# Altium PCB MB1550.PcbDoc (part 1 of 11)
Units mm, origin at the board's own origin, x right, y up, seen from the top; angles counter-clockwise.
Board outline 154.81 x 170.69 mm, 6 copper layers (Top Layer, Signal Layer 1, Signal Layer 2, Signal Layer 3, Signal Layer 4, Bottom Layer), stack 1.49 mm thick; 810 components, 633 nets, 2973 pads, 2150 vias.
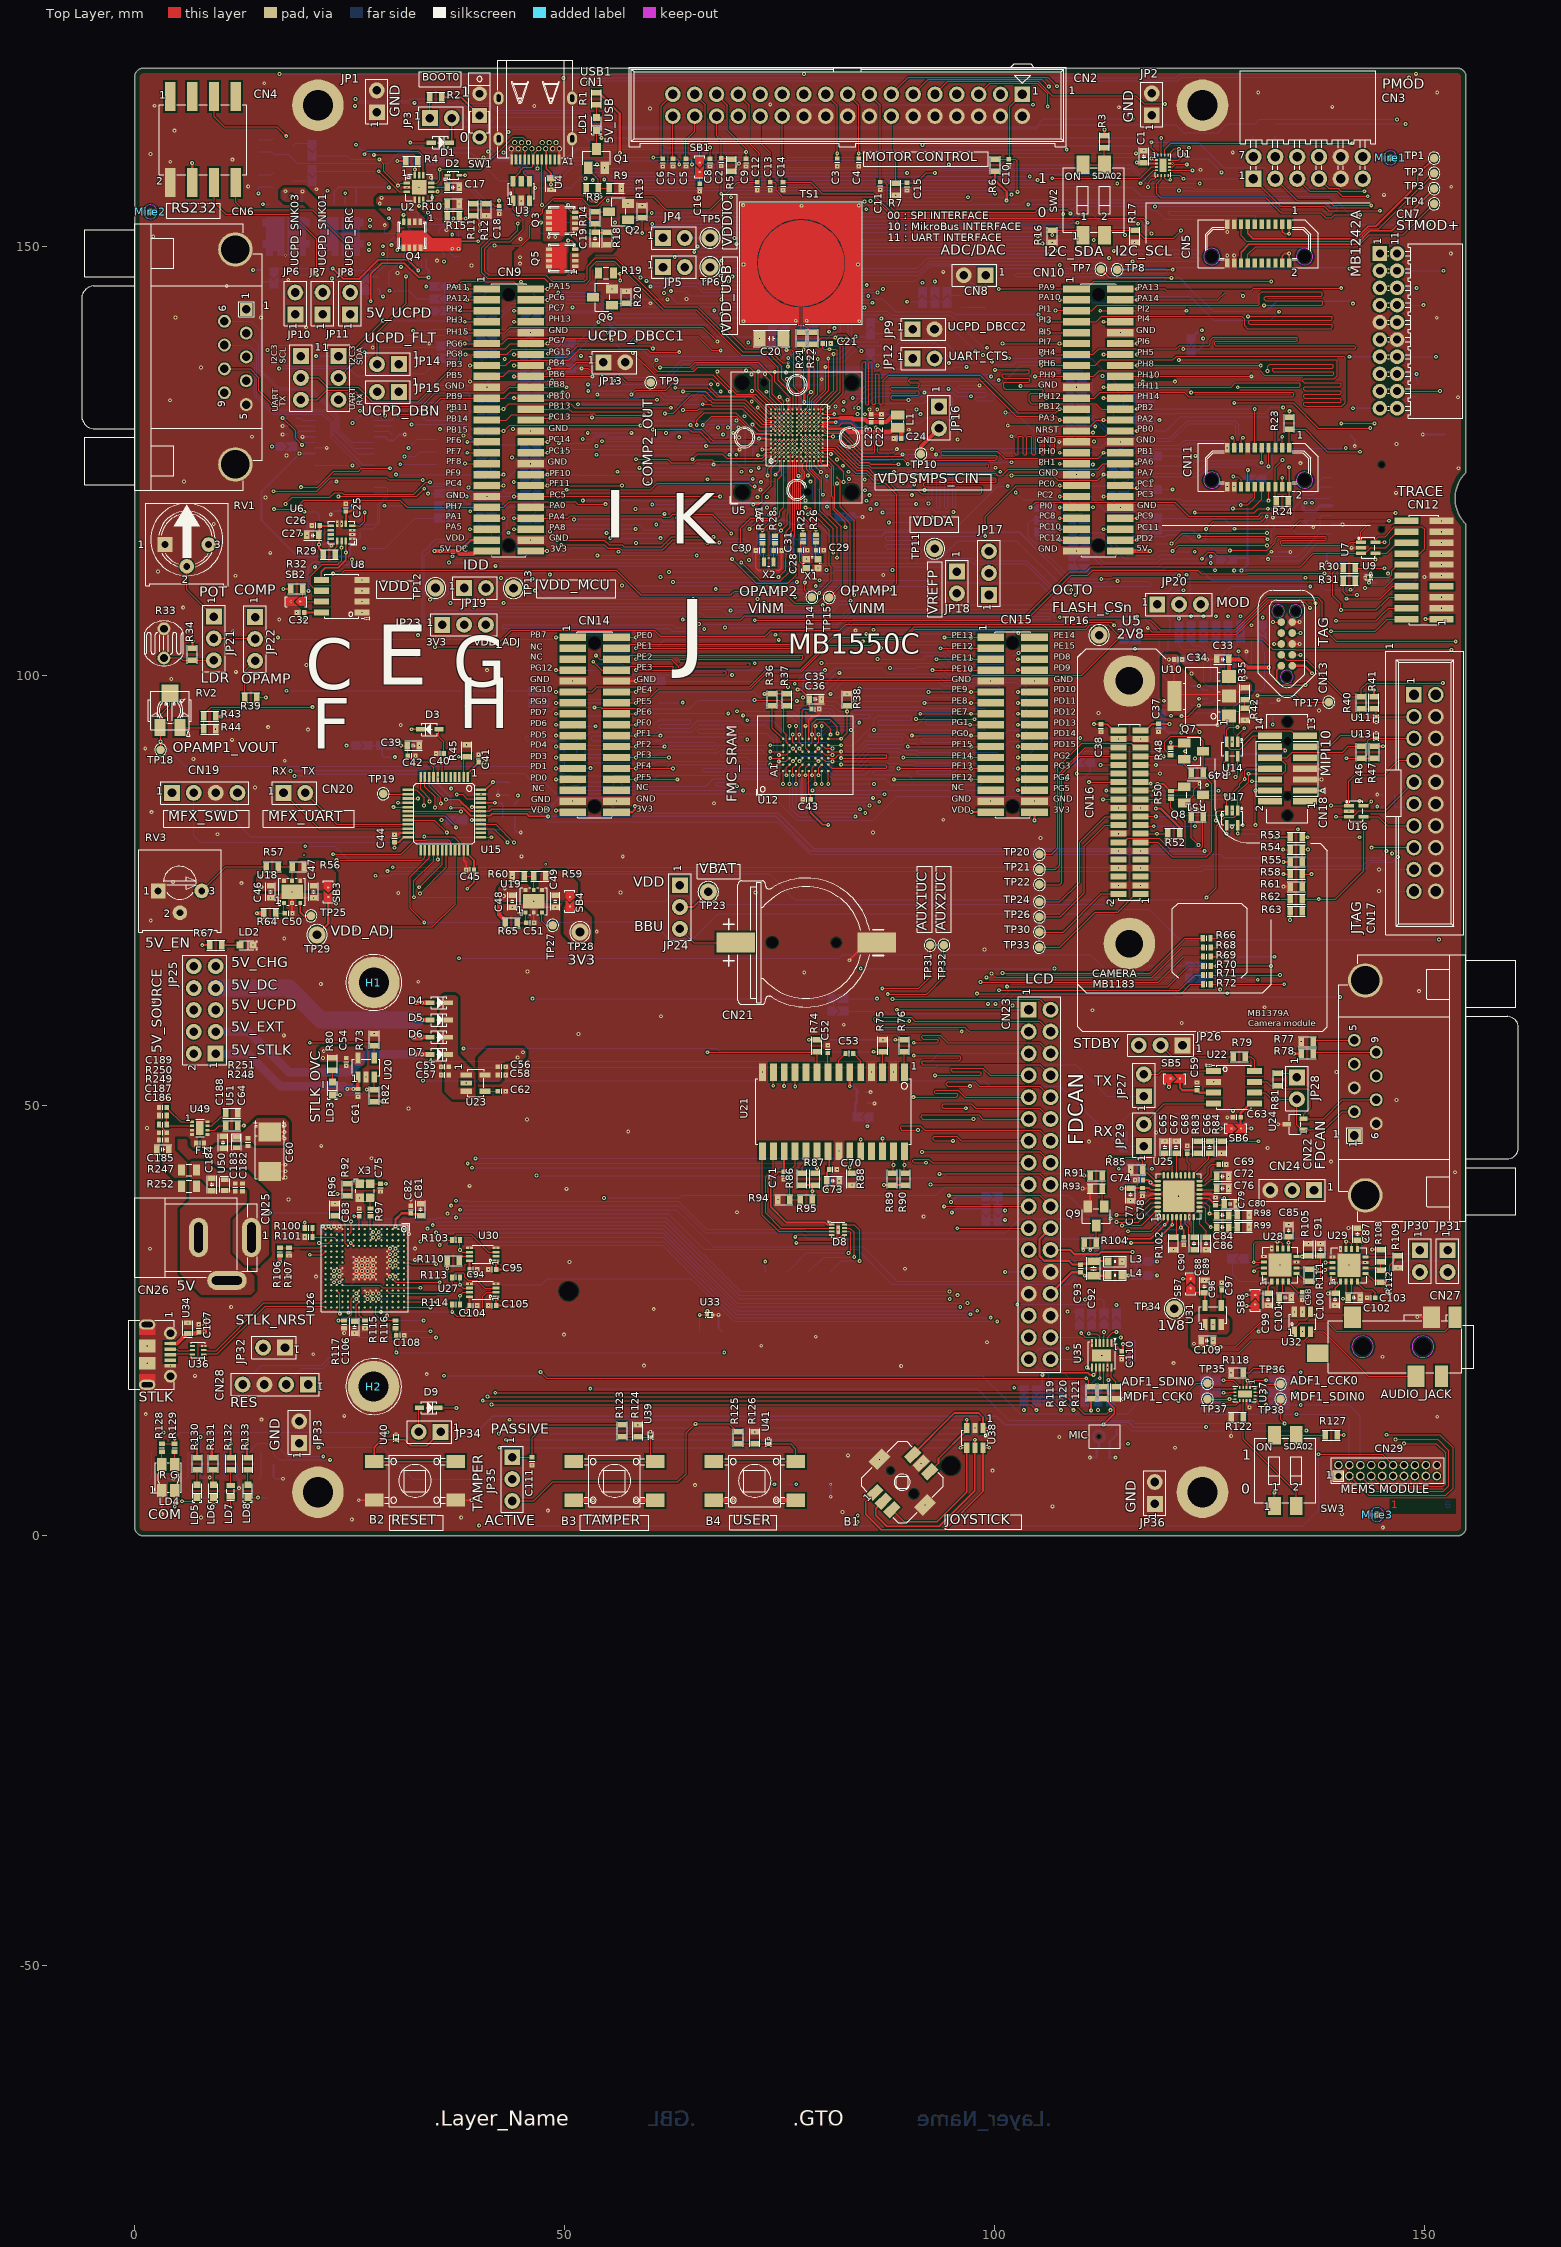
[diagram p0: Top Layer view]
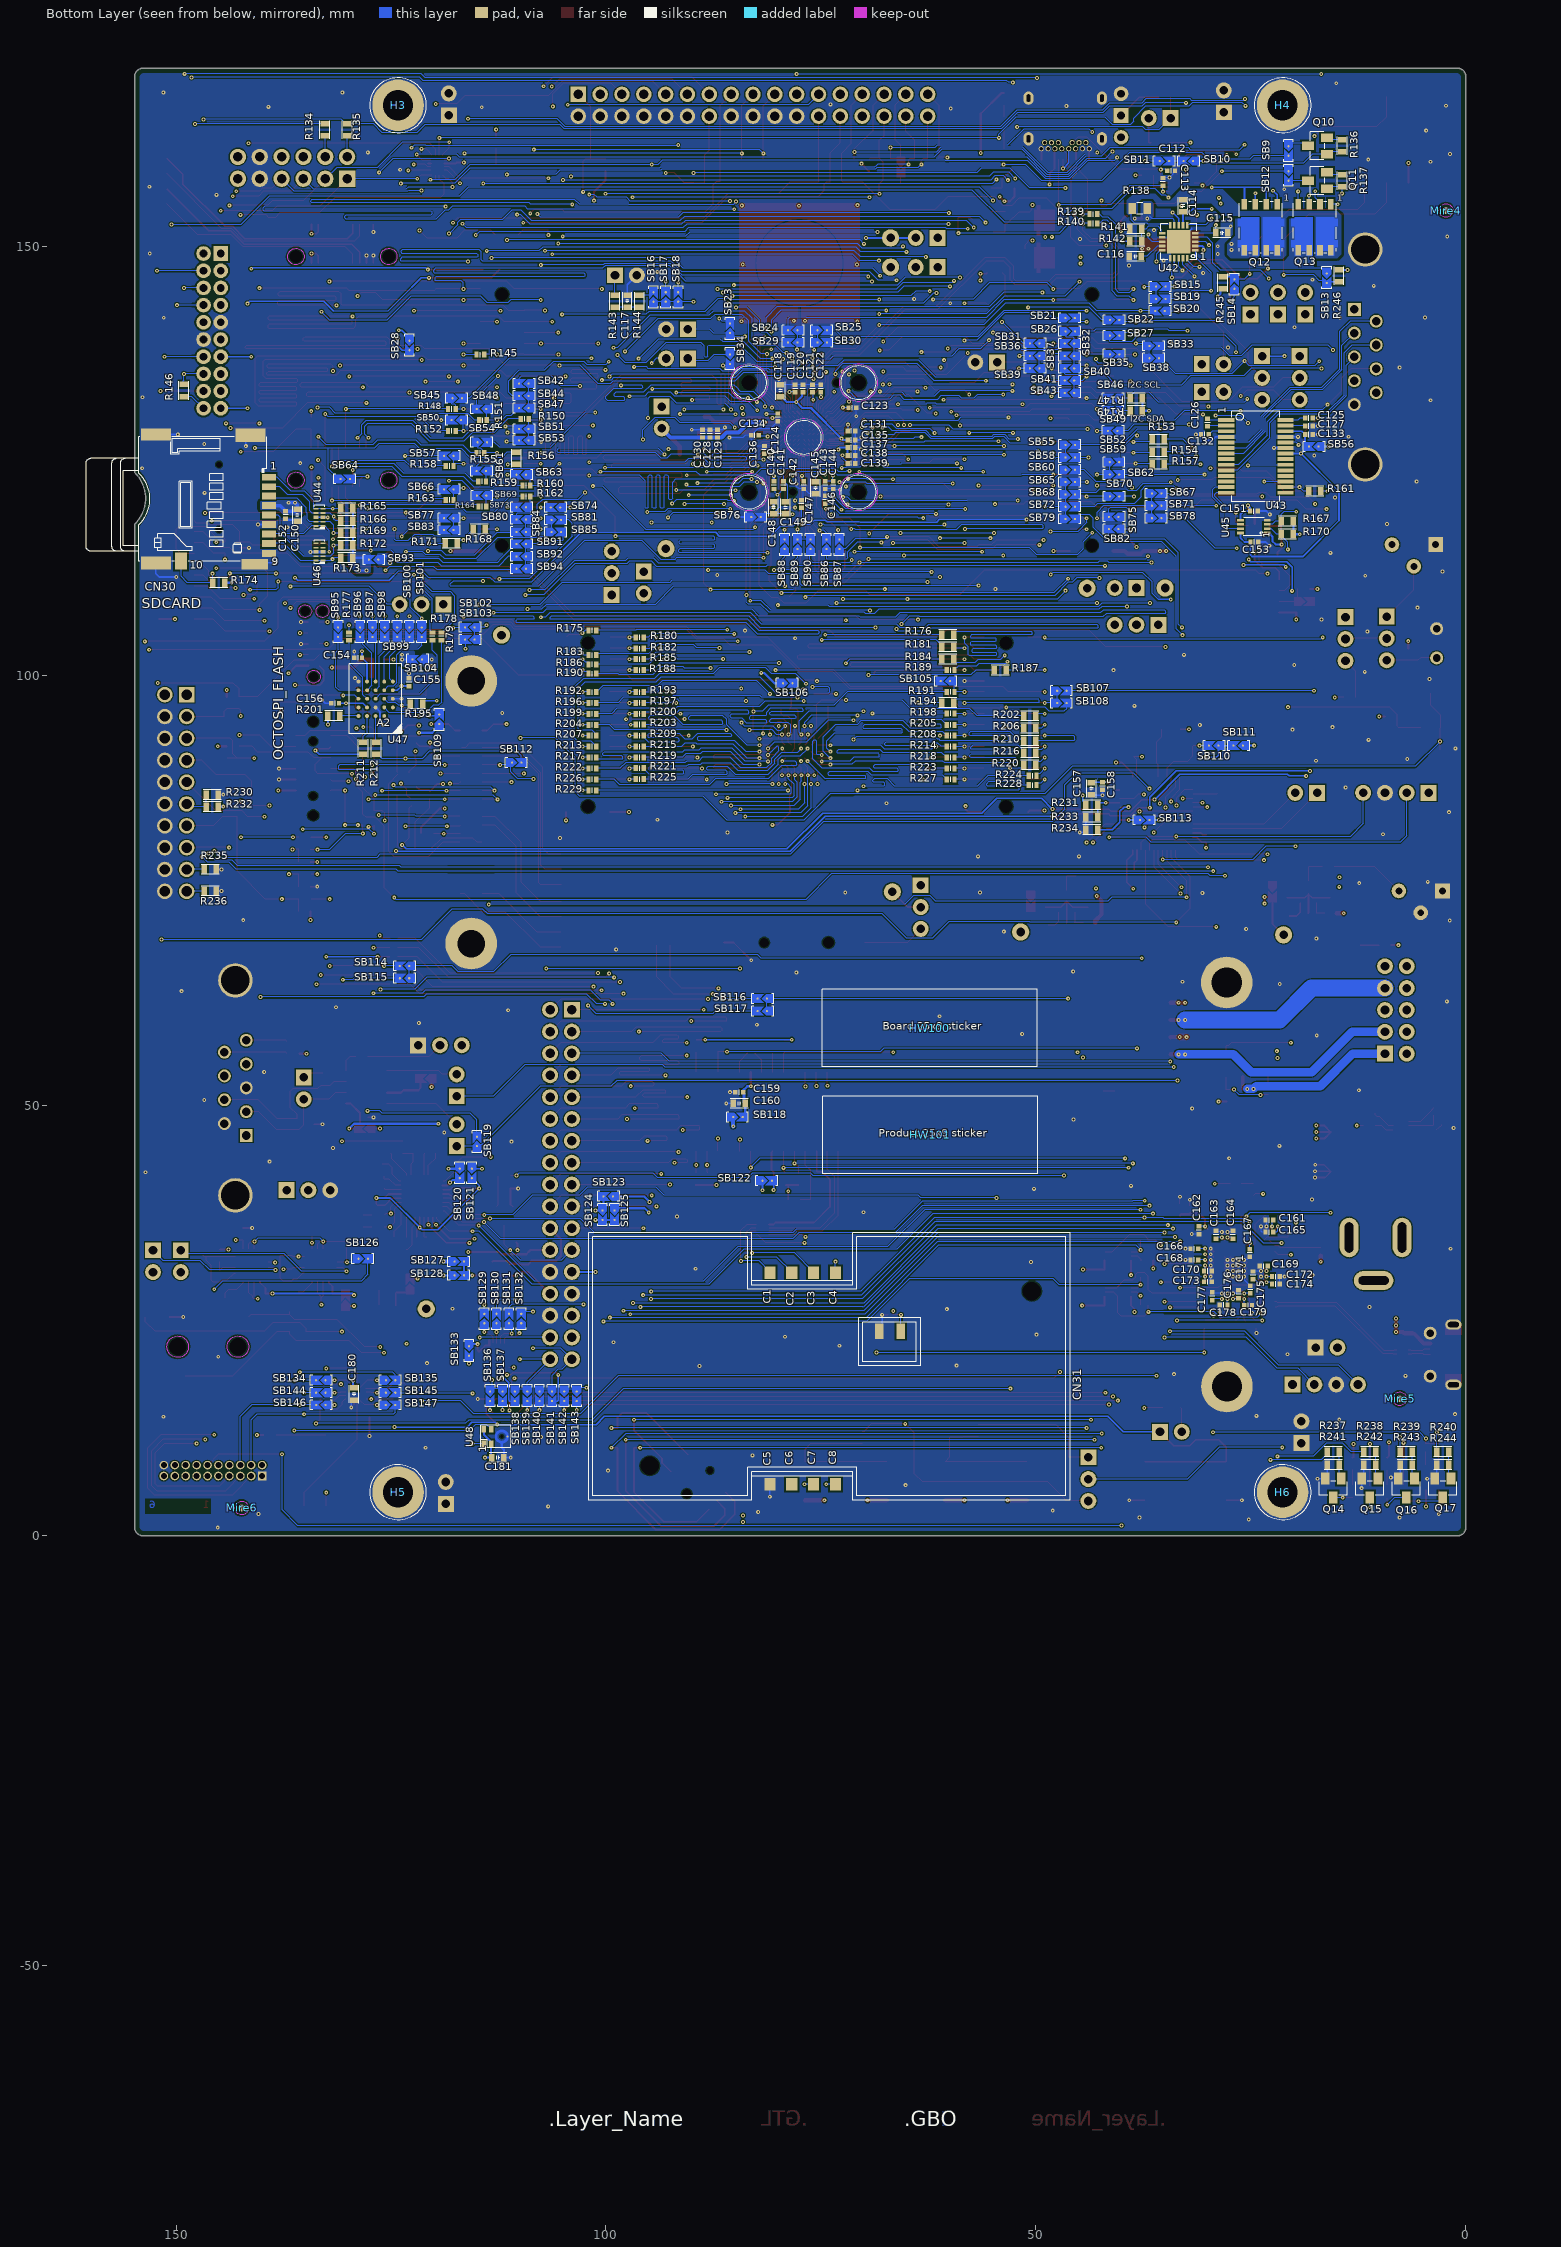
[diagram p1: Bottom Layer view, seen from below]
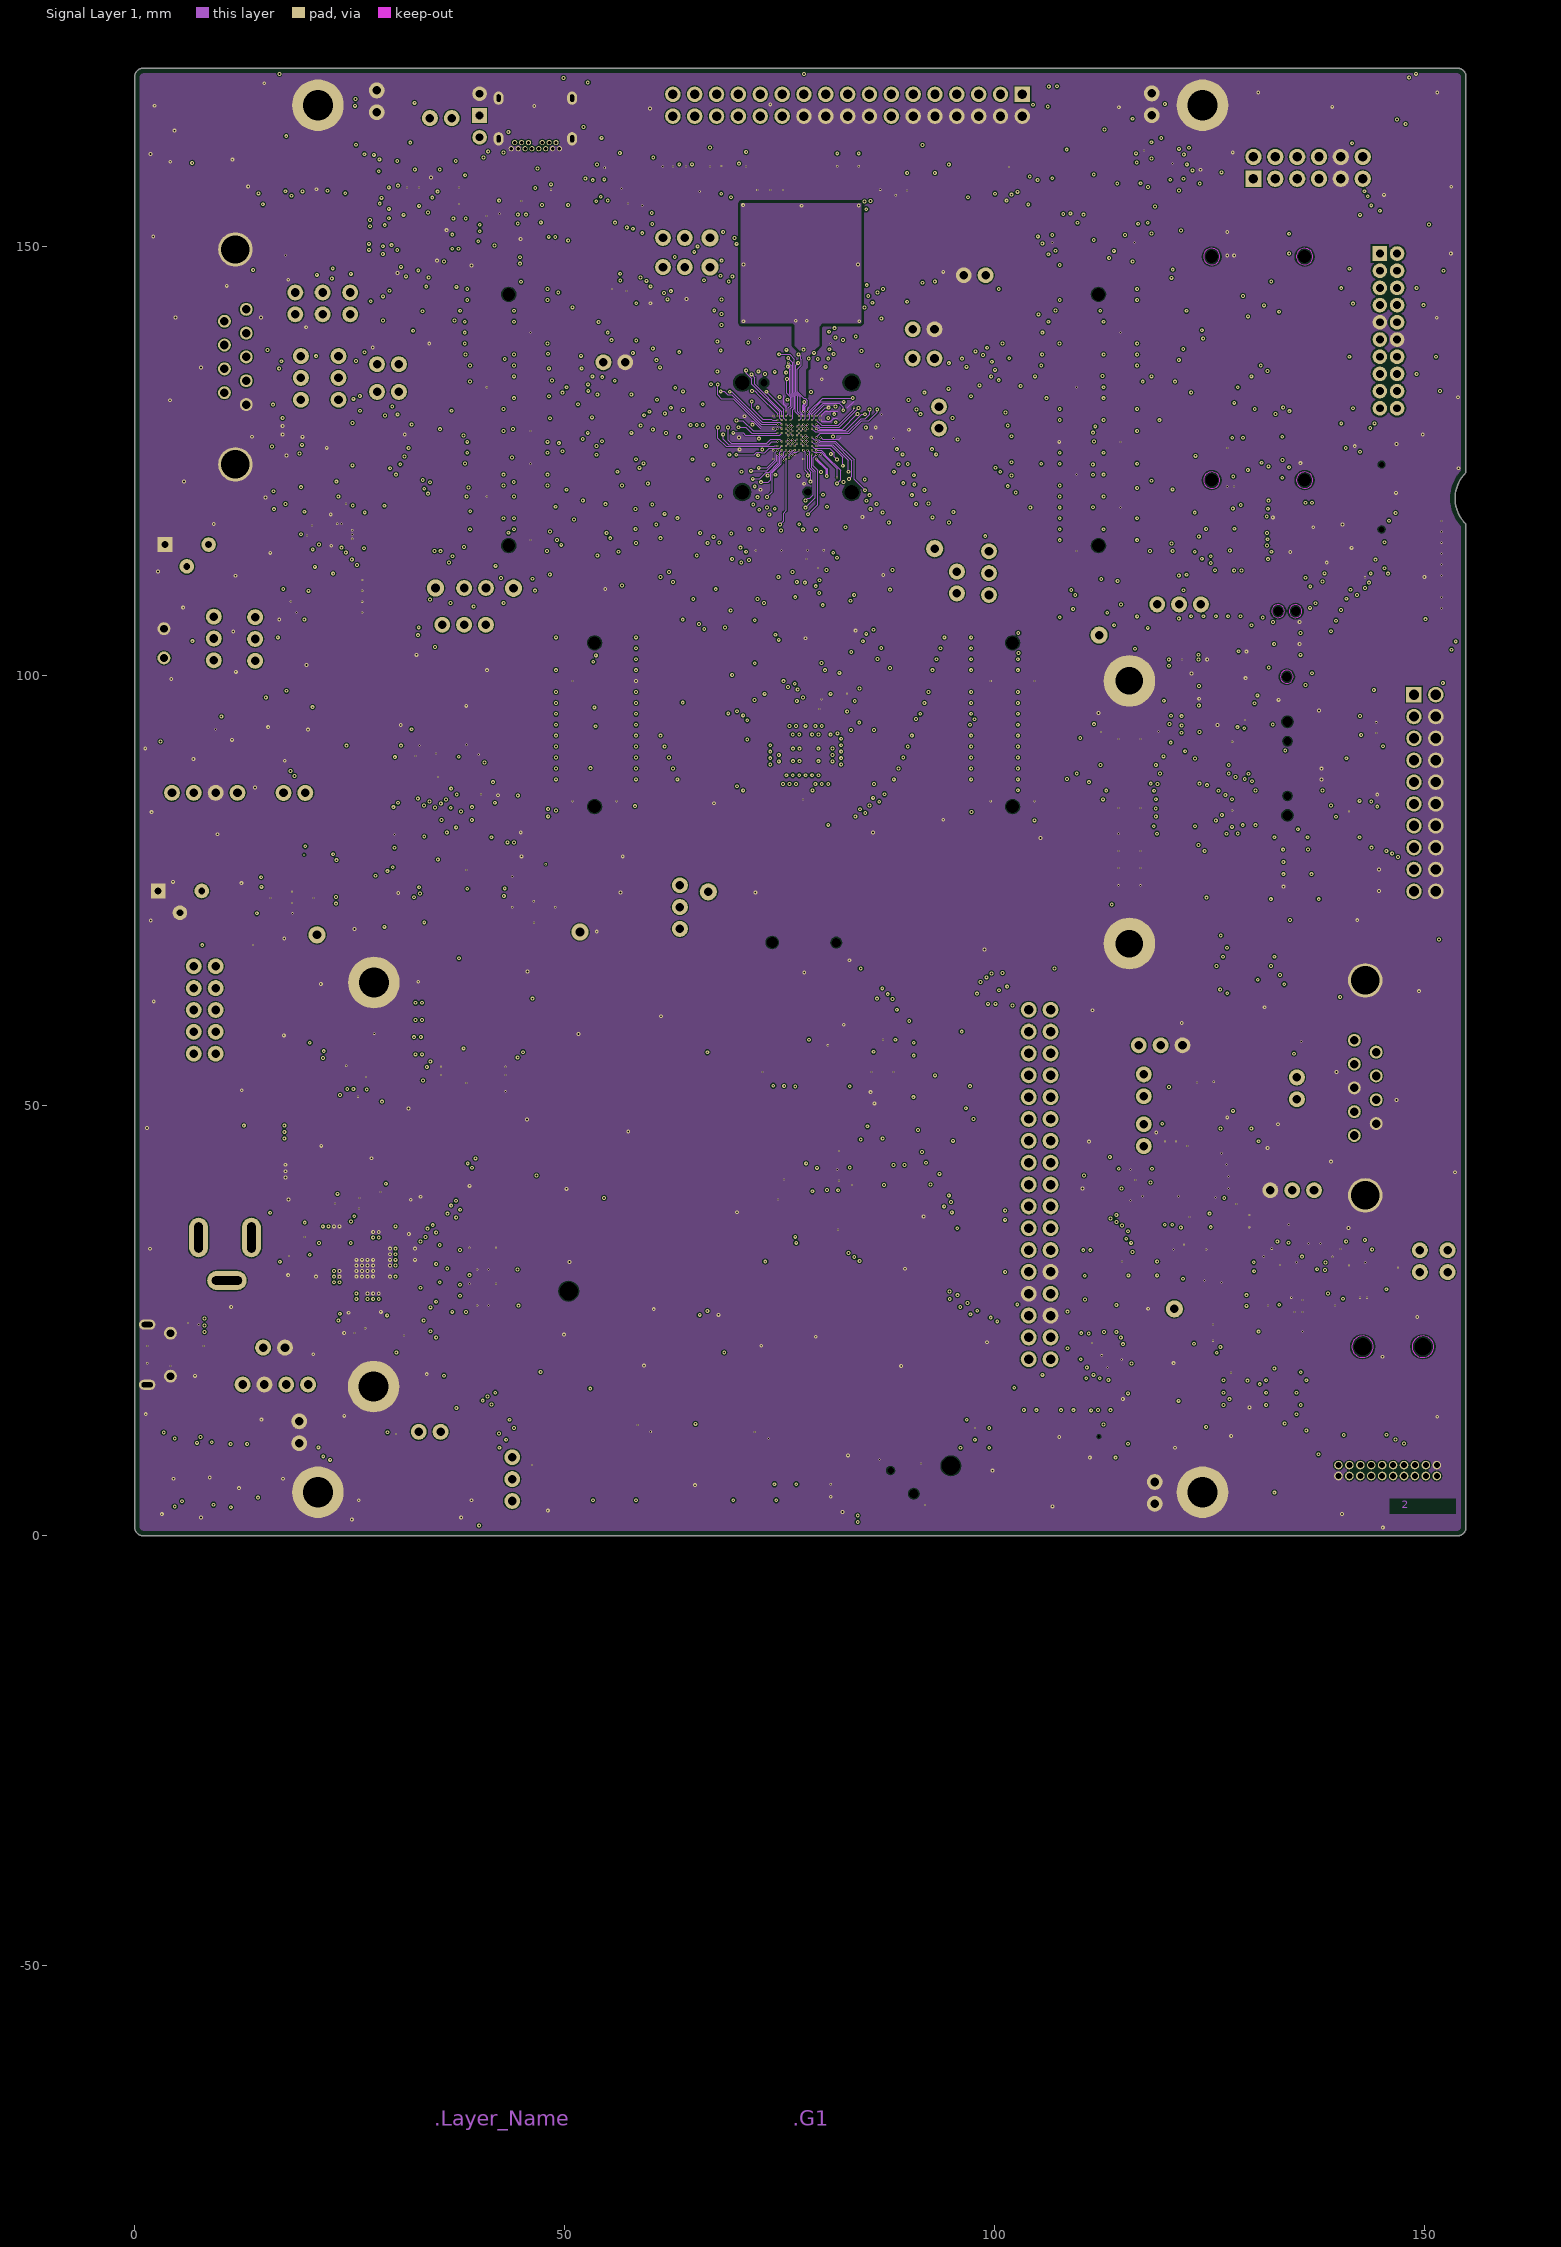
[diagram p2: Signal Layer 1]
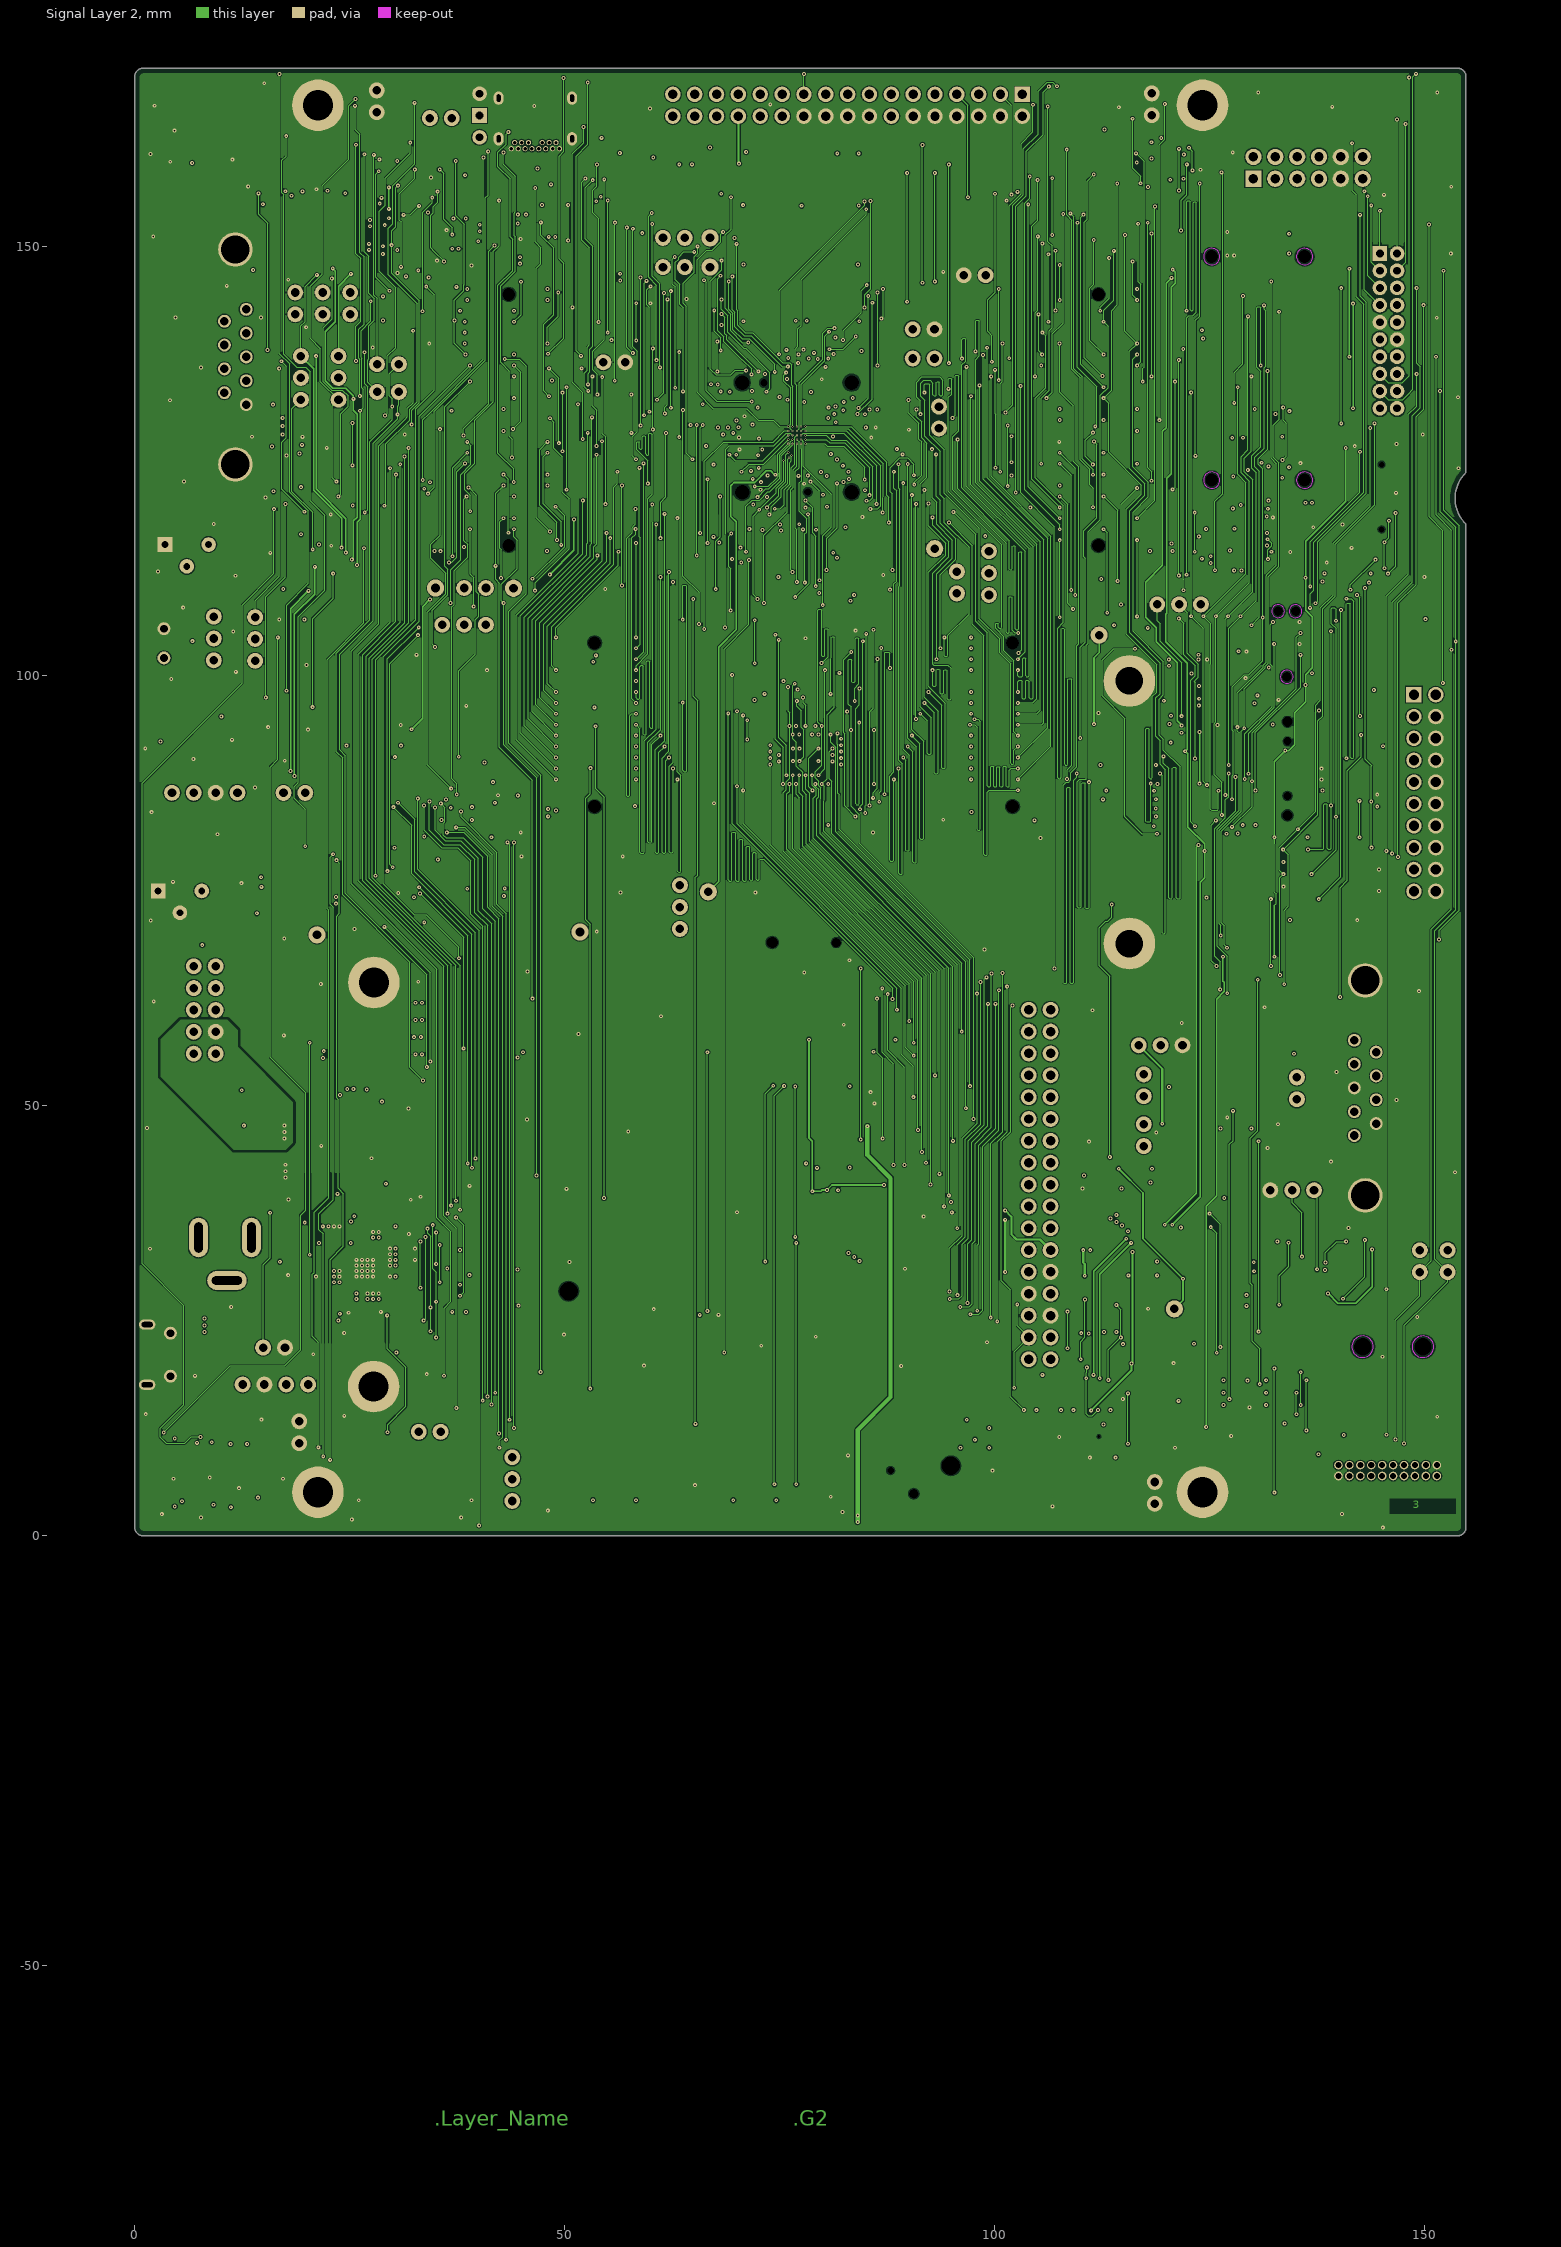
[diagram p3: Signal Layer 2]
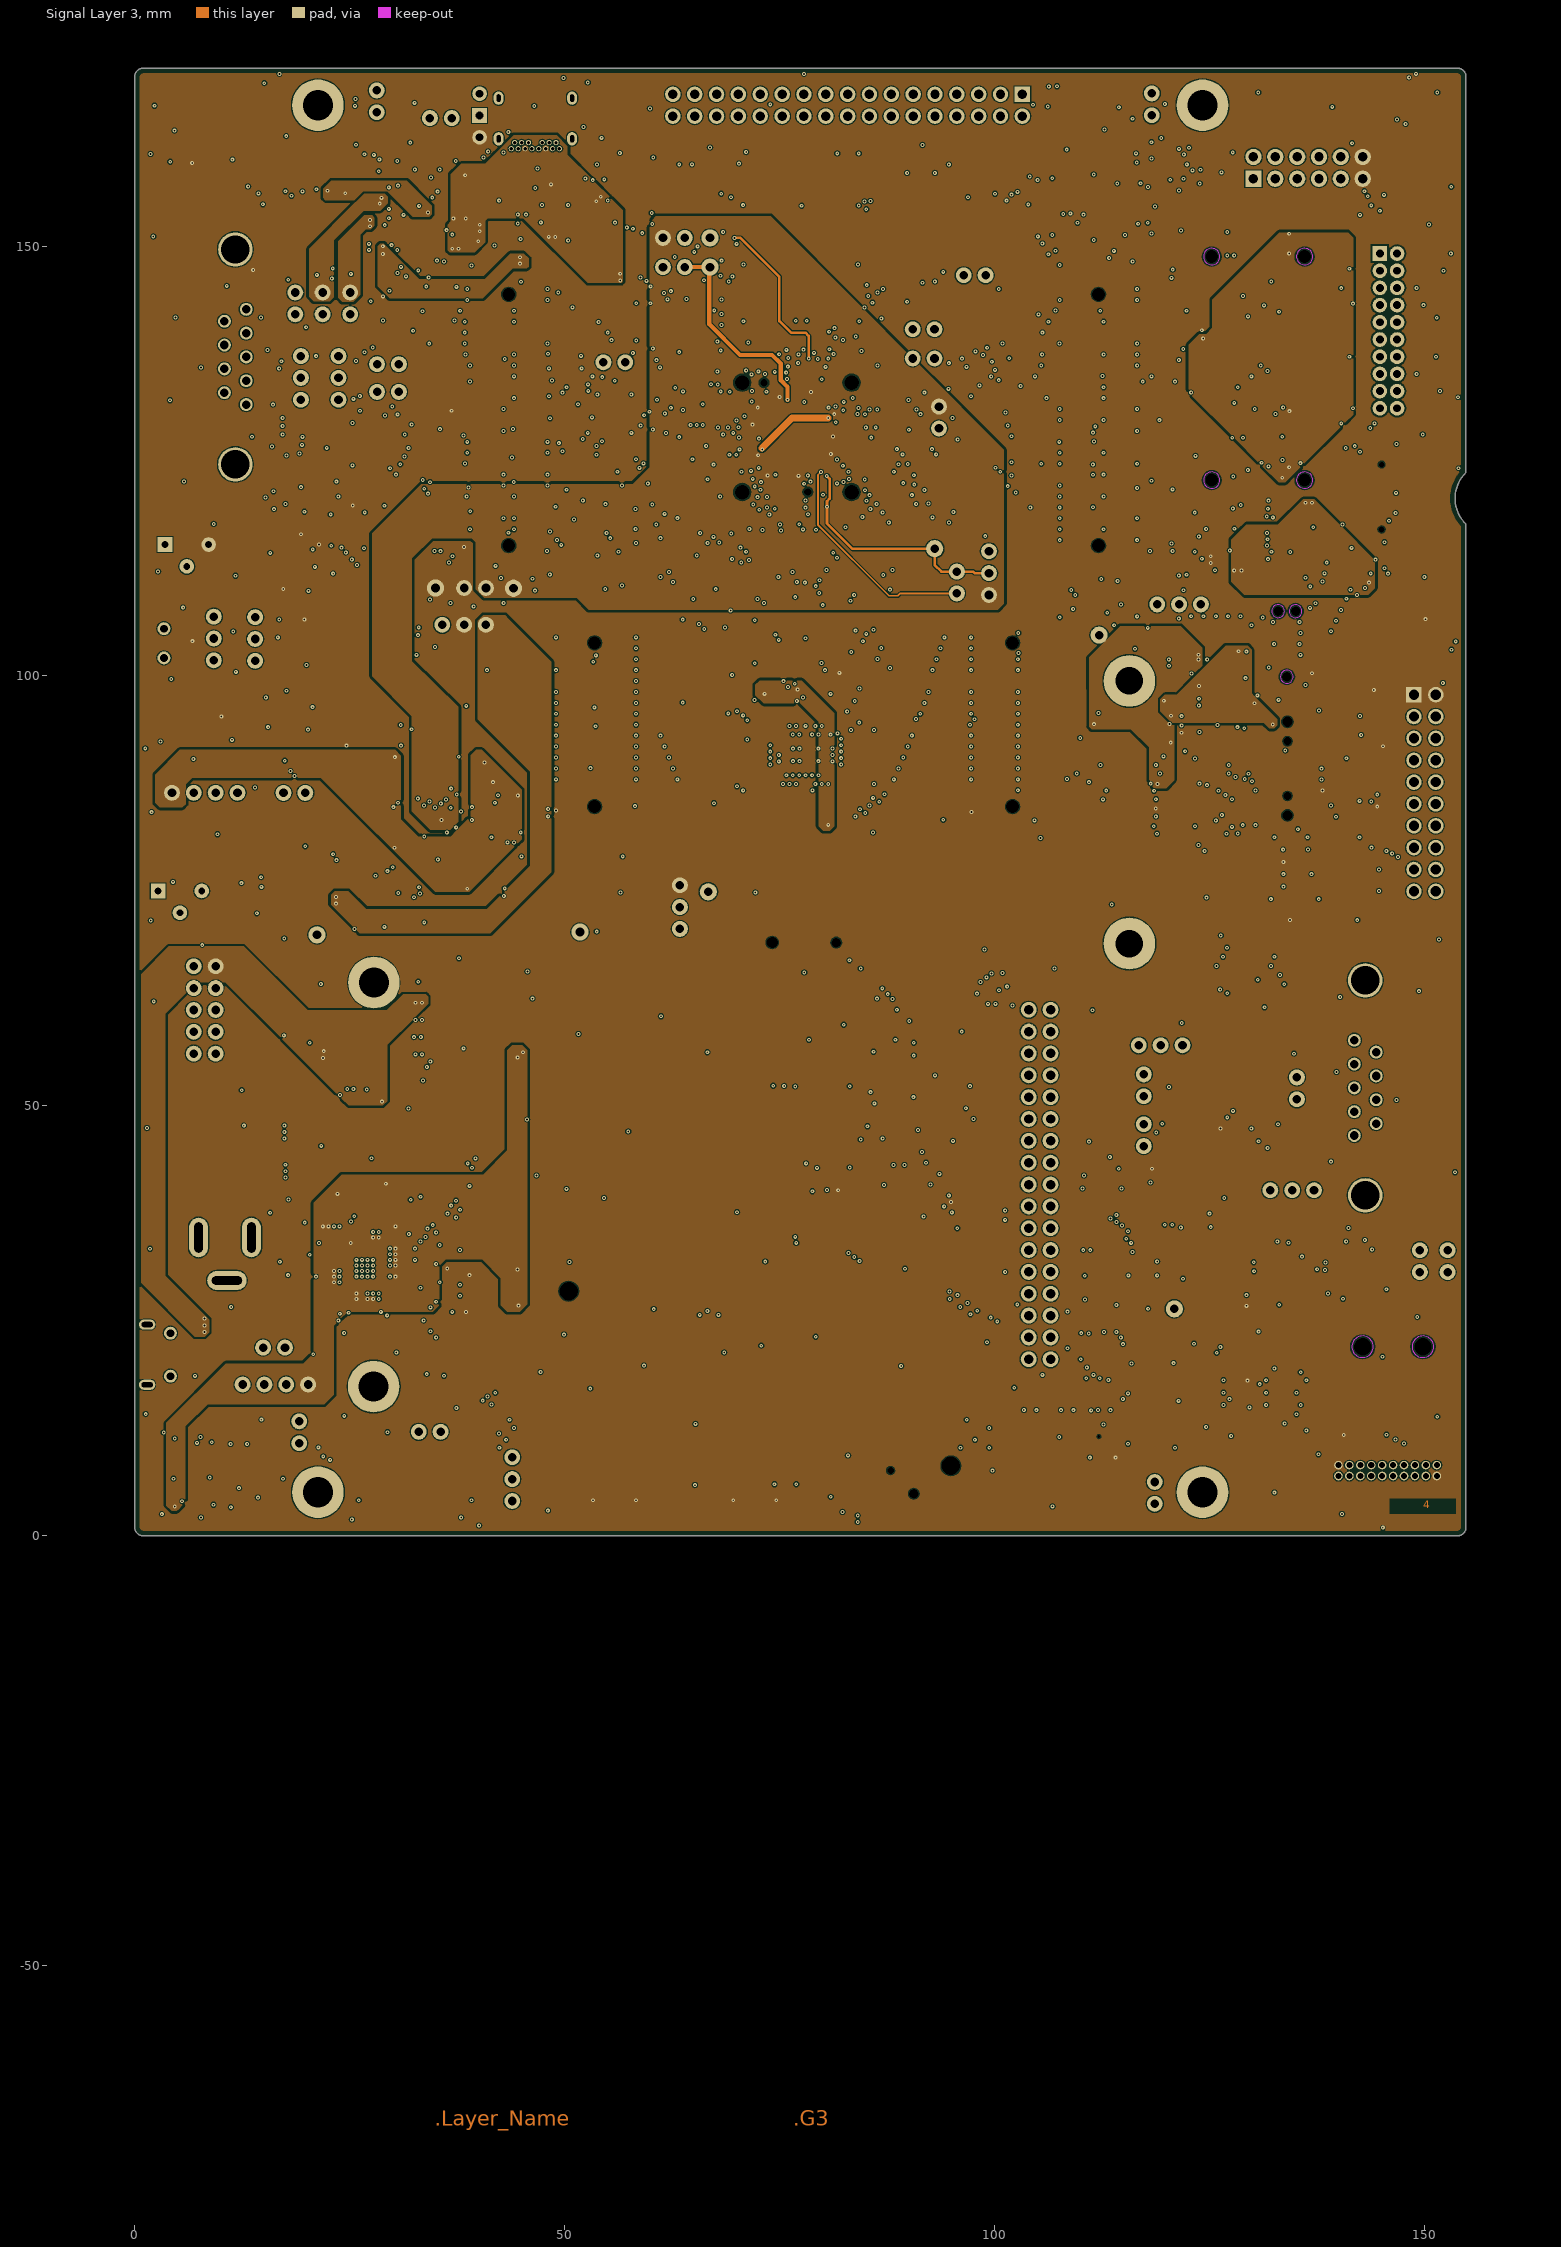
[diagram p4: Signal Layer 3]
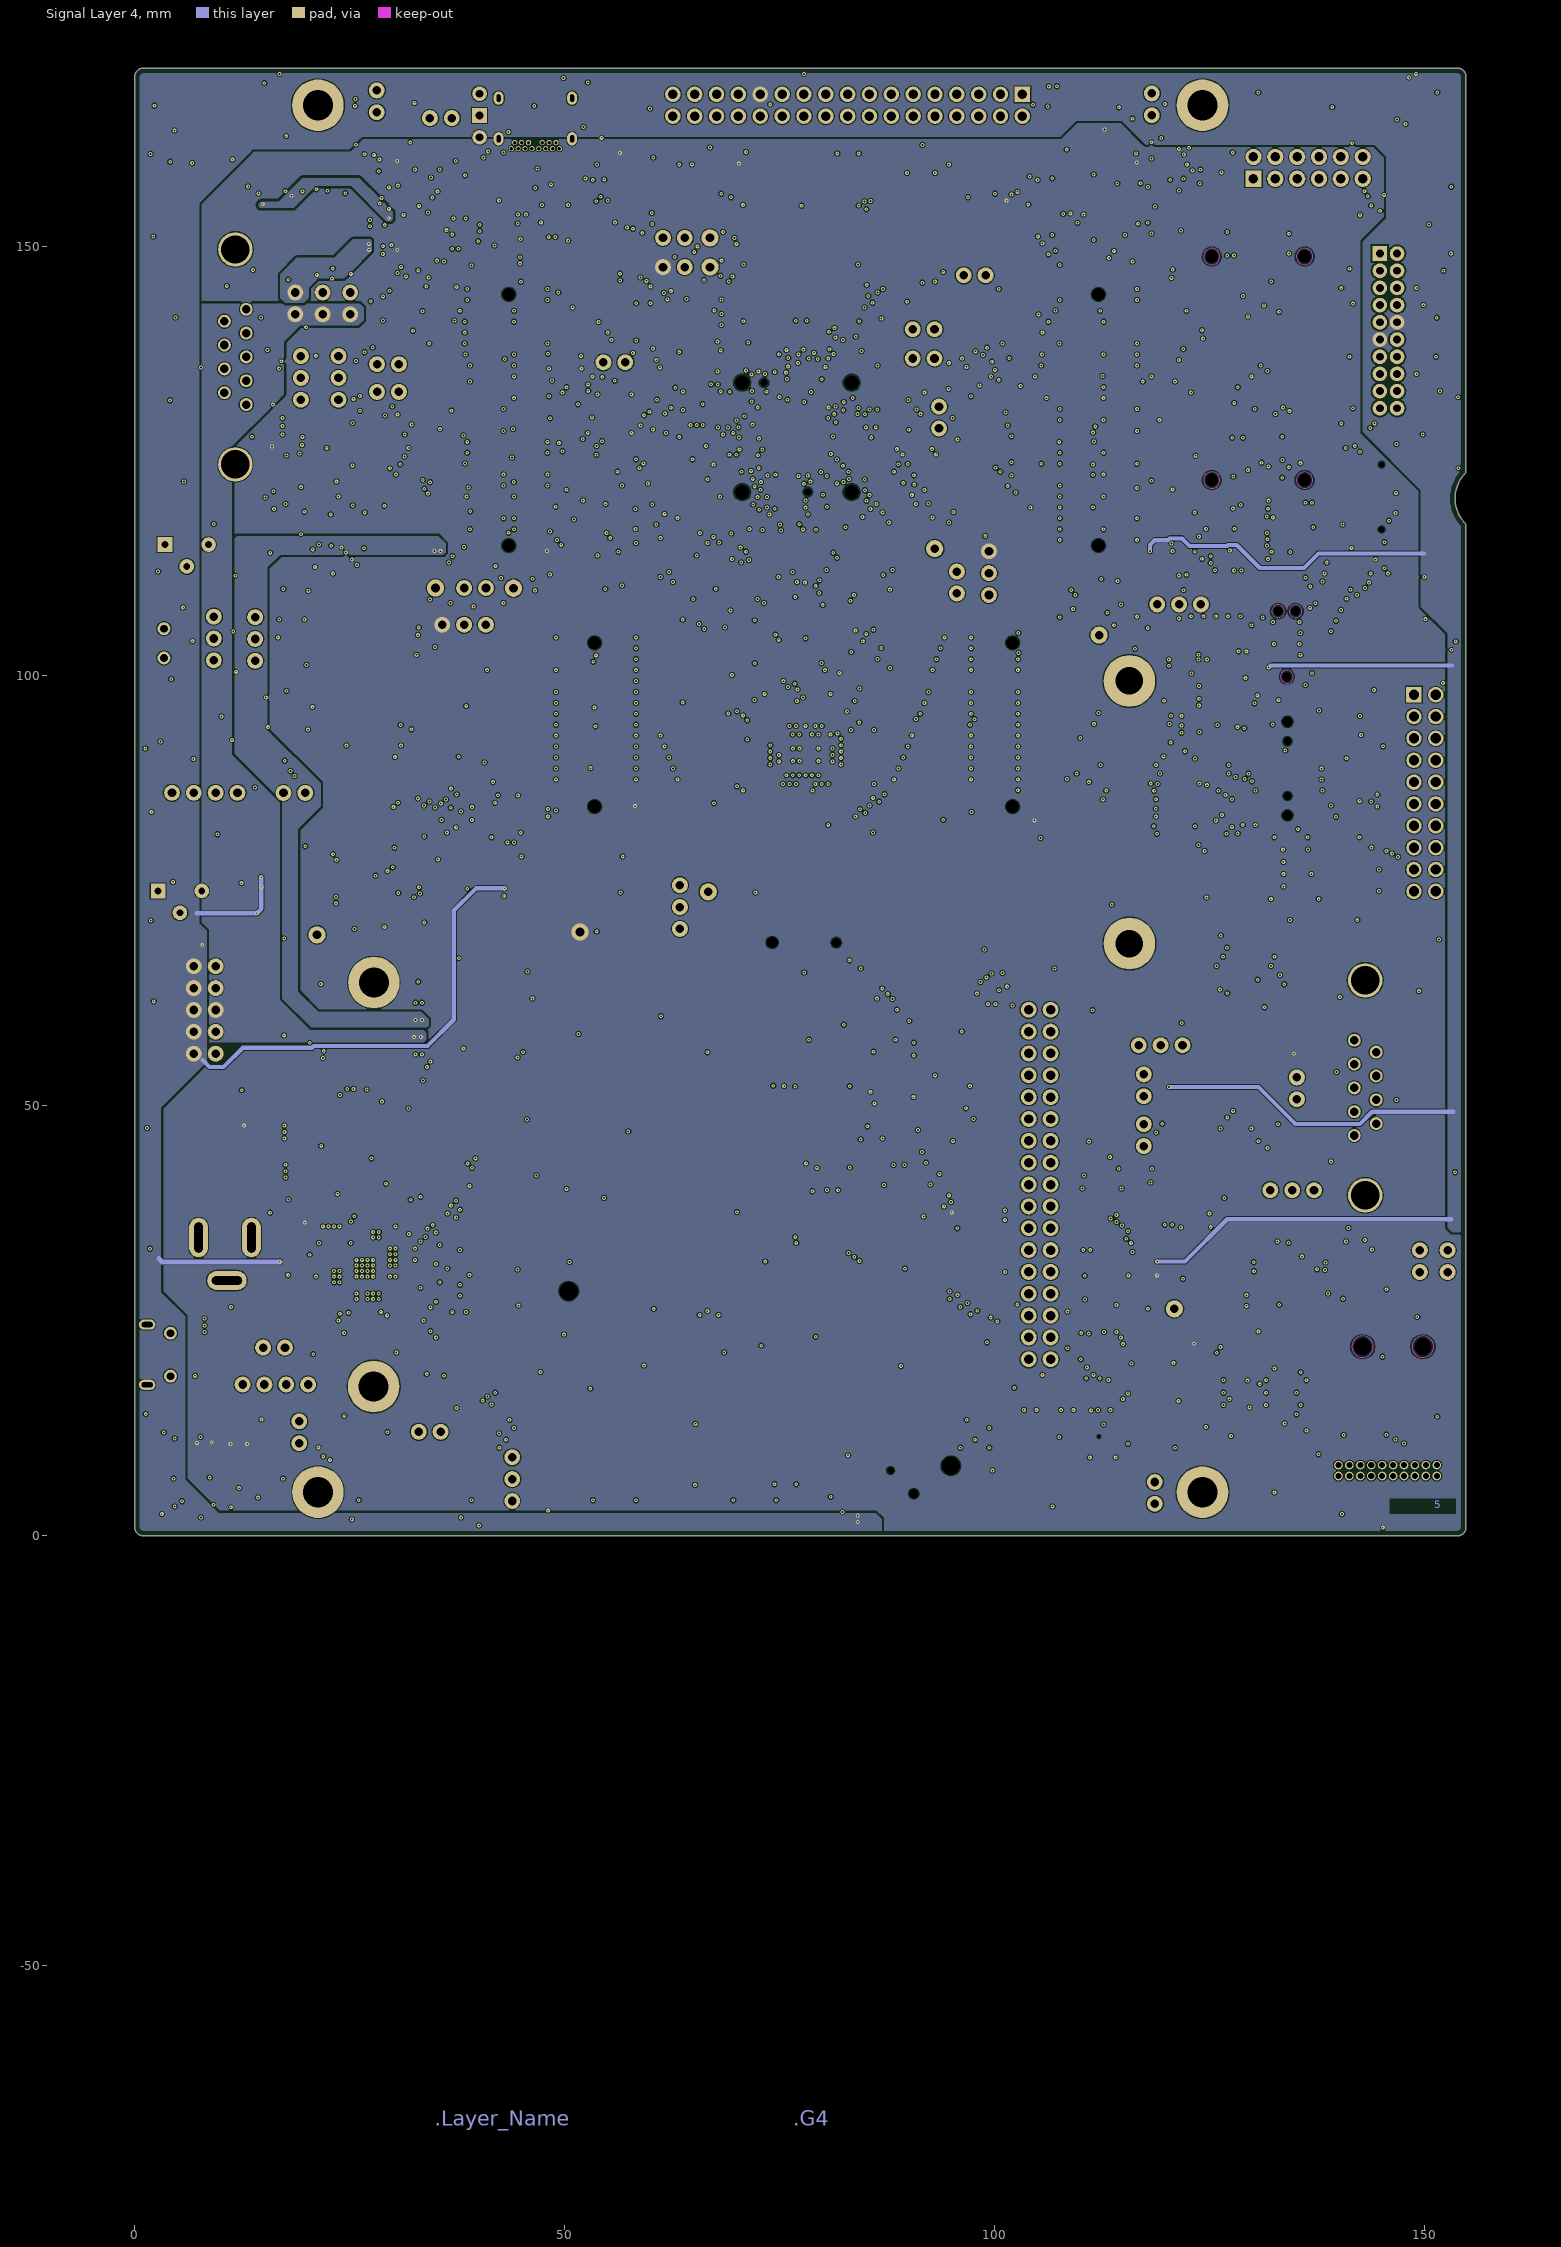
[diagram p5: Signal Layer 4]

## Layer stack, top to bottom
Top Solder: solder mask 0.015, Solder Resist, Dk 3.5
Top Layer: signal copper 0.035
Dielectric 1: prepreg 0.07, TU-768P, Dk 4.2
Signal Layer 1: signal copper 0.035
Dielectric 2: core 0.07, TU-768P, Dk 4.2
Signal Layer 2: signal copper 0.035
Dielectric 3: prepreg 1, TU-768, Dk 4.2
Signal Layer 3: signal copper 0.035
Dielectric 4: core 0.07, TU-768P, Dk 4.2
Signal Layer 4: signal copper 0.035
Dielectric 5: prepreg 0.07, TU-768P, Dk 4.2
Bottom Layer: signal copper 0.035
Bottom Solder: solder mask 0.015, Solder Resist, Dk 3.5

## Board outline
0,1 ccw(c1,1) 1,0 153.813,0 ccw(c153.813,1) 154.813,1 154.813,117.648 154.811,117.648 cw(c157.726,120.648) 154.813,123.65 154.813,169.688 ccw(c153.813,169.688) 153.813,170.688 1,170.688 ccw(c1,169.688) 0,169.688

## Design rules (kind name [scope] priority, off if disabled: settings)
BoardOutlineClearance BoardOutlineClearance_2 [OnLayer('Bottom Overlay')] p1: gap=0 ignorepadtopadclearanceinfootprint=FALSE
BoardOutlineClearance BoardOutlineClearance_1 [OnLayer('Top Overlay')] p2: gap=0 ignorepadtopadclearanceinfootprint=FALSE
BoardOutlineClearance [All] p3: gap=0.6 ignorepadtopadclearanceinfootprint=FALSE
Clearance Clearance_BGA_MCU [WithinRoom('RoomDefinition')and TouchesRoom('RoomDefinition')] p1: gap=0.085 ignorepadtopadclearanceinfootprint=TRUE except(0: Arc-Hole Track-Hole SMDPad-Hole THPad-Hole Via-Hole Fill-Hole Poly-Hole Region-Hole Text-Hole; 0.12: Via-Poly; 0.14: Track-Poly; 0.15: SMDPad-SMDPad; 0.2: Arc-Fill Arc-Poly Track-Fill SMDPad-THPad SMDPad-Fill SMDPad-Poly THPad-THPad THPad-Fill THPad-Poly Via-Fill Fill-Poly; 0.3: Fill-Fill Poly-Poly)
Clearance Clearance_BGA_SRAM [WithinRoom('RoomDefinition_1')and TouchesRoom('RoomDefinition_1')] p2: gap=0.09 ignorepadtopadclearanceinfootprint=TRUE except(0: Arc-Hole Track-Hole SMDPad-Hole THPad-Hole Via-Hole Fill-Hole Poly-Hole Region-Hole Text-Hole; 0.12: Via-Poly; 0.15: SMDPad-SMDPad; 0.2: Arc-Fill Arc-Poly Track-Fill Track-Poly SMDPad-THPad SMDPad-Fill SMDPad-Poly THPad-THPad THPad-Fill THPad-Poly Via-Fill Fill-Poly; 0.3: Fill-Fill Poly-Poly)
Clearance Clearance_BGA_STLINK [WithinRoom('RoomDefinition_2')and TouchesRoom('RoomDefinition_2')] p3: gap=0.09 ignorepadtopadclearanceinfootprint=TRUE except(0: Arc-Hole Track-Hole SMDPad-Hole THPad-Hole Via-Hole Fill-Hole Poly-Hole Region-Hole Text-Hole; 0.12: Via-Poly; 0.15: SMDPad-SMDPad; 0.2: Arc-Fill Arc-Poly Track-Fill Track-Poly SMDPad-THPad SMDPad-Fill SMDPad-Poly THPad-THPad THPad-Fill THPad-Poly Via-Fill Fill-Poly; 0.3: Fill-Fill Poly-Poly)
Clearance Clearance_CONN [WithinRoom('RoomDefinition_3','RoomDefinition_4')and TouchesRoom('RoomDefinition_3','RoomDefinition_4')] p4: gap=0.1 ignorepadtopadclearanceinfootprint=TRUE except(0: Arc-Hole Track-Hole SMDPad-Hole THPad-Hole Via-Hole Fill-Hole Poly-Hole Region-Hole Text-Hole; 0.12: Via-Poly; 0.15: SMDPad-SMDPad; 0.2: Arc-Fill Arc-Poly Track-Fill Track-Poly SMDPad-THPad SMDPad-Fill SMDPad-Poly THPad-THPad THPad-Fill THPad-Poly Via-Fill Fill-Poly; 0.3: Fill-Fill Poly-Poly)
Clearance Clearance_50Ohms [InNetClass('50 Ohms')] p5: gap=0.12 ignorepadtopadclearanceinfootprint=TRUE except(0: Arc-Hole Track-Hole SMDPad-Hole THPad-Hole Via-Hole Fill-Hole Poly-Hole Region-Hole Text-Hole; 0.15: SMDPad-SMDPad; 0.2: Arc-Fill Arc-Poly SMDPad-THPad SMDPad-Fill SMDPad-Poly THPad-THPad THPad-Fill Via-Via Via-Fill Fill-Poly; 0.23: Arc-Track Track-Track; 0.29: Track-Fill Track-Poly; 0.3: Fill-Fill Poly-Poly)
Clearance [All] p6: gap=0.12 ignorepadtopadclearanceinfootprint=TRUE except(0: Arc-Hole Track-Hole SMDPad-Hole THPad-Hole Via-Hole Fill-Hole Poly-Hole Region-Hole Text-Hole; 0.15: SMDPad-SMDPad; 0.2: Arc-Fill Arc-Poly Track-Fill SMDPad-THPad SMDPad-Fill SMDPad-Poly THPad-THPad THPad-Fill Via-Via Via-Fill Fill-Poly; 0.3: Fill-Fill Poly-Poly)
ComponentClearance [All] p1 off: gap=0.025 collisioncheckmode=3 verticalgap=0 showdistances=FALSE
DiffPairsRouting DiffPairsRouting_90_ohms [InDifferentialPairClass('90Ohms_Diff')] p1: maxlimit=0.26 minlimit=0.251 mostfreqgap=0.251 toplayer_mingap=0.26 toplayer_prefgap=0.26 toplayer_minwidth=0.12 toplayer_maxwidth=0.12 toplayer_prefwidth=0.12 midlayer1_maxgap=0.251 midlayer1_minwidth=0.13 midlayer1_maxwidth=0.13 midlayer1_prefwidth=0.13 midlayer2_maxgap=0.251 midlayer2_minwidth=0.13 midlayer2_maxwidth=0.13 midlayer2_prefwidth=0.13 midlayer3_maxgap=0.251 midlayer3_minwidth=0.13 midlayer3_maxwidth=0.13 midlayer3_prefwidth=0.13 midlayer4_maxgap=0.251 midlayer4_minwidth=0.13 midlayer4_maxwidth=0.13 midlayer4_prefwidth=0.13 bottomlayer_mingap=0.26 bottomlayer_prefgap=0.26 bottomlayer_minwidth=0.12 bottomlayer_maxwidth=0.12 bottomlayer_prefwidth=0.12 maxuncoupledlength=12.7
DiffPairsRouting DiffPairsRouting_100_ohms [InDifferentialPairClass('100Ohms_Diff')] p2: maxlimit=0.277 minlimit=0.251 mostfreqgap=0.277 toplayer_maxgap=0.251 toplayer_prefgap=0.251 toplayer_minwidth=0.13 toplayer_maxwidth=0.13 toplayer_prefwidth=0.13 midlayer1_mingap=0.277 midlayer1_minwidth=0.104 midlayer1_maxwidth=0.104 midlayer1_prefwidth=0.104 midlayer2_mingap=0.277 midlayer2_minwidth=0.104 midlayer2_maxwidth=0.104 midlayer2_prefwidth=0.104 midlayer3_mingap=0.277 midlayer3_minwidth=0.104 midlayer3_maxwidth=0.104 midlayer3_prefwidth=0.104 midlayer4_mingap=0.277 midlayer4_minwidth=0.104 midlayer4_maxwidth=0.104 midlayer4_prefwidth=0.104 bottomlayer_maxgap=0.251 bottomlayer_prefgap=0.251 bottomlayer_minwidth=0.13 bottomlayer_maxwidth=0.13 bottomlayer_prefwidth=0.13 maxuncoupledlength=12.7
FanoutControl Fanout_LCC [IsLCC] p1: bgadir=Out bgaviamode=Centered fanoutstyle=Auto fanoutdirection=Alternating viagrid=0.025 // Fanout_LCC (Default Rule)
FanoutControl Fanout_SOIC [IsSOIC] p2: bgadir=Out bgaviamode=Centered fanoutstyle=Auto fanoutdirection=Alternating viagrid=0.025 // Fanout_SOIC (Default Rule)
FanoutControl Fanout_Small [(CompPinCount < 5)] p3: bgadir=Out bgaviamode=Centered fanoutstyle=Auto fanoutdirection=OutThenIn viagrid=0.025 // Fanout_Small (Default Rule)
FanoutControl Fanout_Default [All] p4: bgadir=Out bgaviamode=Centered fanoutstyle=Auto fanoutdirection=Alternating viagrid=0.025 // Fanout_Default (Default Rule)
HoleSize [All] p1: absolutevalues=TRUE maxlimit=10 minlimit=0.025 maxpercent=80.000 minpercent=20.000
HoleToHoleClearance [InDrillLayerPair('Top Layer - Bottom Layer') vs InDrillLayerPair('Top Layer - Bottom Layer')] p1: gap=0.5 allowstackedmicrovias=TRUE
MatchedLengths MatchedLengths_TRACE [InNetClass('TRACE')] p1: tolerance=7 checknetsindiffpair=FALSE checkdiffpairvsdiffpair=TRUE checkxsignals=TRUE checkothers=TRUE
MatchedLengths MatchedLengths_Camera [InNetClass('Camera')] p2: tolerance=7 checknetsindiffpair=FALSE checkdiffpairvsdiffpair=TRUE checkxsignals=TRUE checkothers=TRUE
MatchedLengths MatchedLengths_JTAG_MCU [InNetClass('JTAG_MCU')] p3: tolerance=10 checknetsindiffpair=FALSE checkdiffpairvsdiffpair=TRUE checkxsignals=TRUE checkothers=TRUE
MatchedLengths MatchedLengths_OCTOSPI_2_MCU [InNetClass('OCTOSPI_2_MCU')] p4: tolerance=7 checknetsindiffpair=FALSE checkdiffpairvsdiffpair=TRUE checkxsignals=TRUE checkothers=TRUE
MatchedLengths MatchedLengths_SRAM_A_MCU [InNetClass('SRAM_A_MCU')] p5: tolerance=7 checknetsindiffpair=FALSE checkdiffpairvsdiffpair=TRUE checkxsignals=TRUE checkothers=TRUE
MatchedLengths MatchedLengths_SDCARD_MCU [InNetClass('SDCARD_MCU')] p6: tolerance=14 checknetsindiffpair=FALSE checkdiffpairvsdiffpair=TRUE checkxsignals=TRUE checkothers=TRUE
MatchedLengths MatchedLengths_OCTOSPI_1_MCU [InNetClass('OCTOSPI_1_MCU')] p7: tolerance=7 checknetsindiffpair=FALSE checkdiffpairvsdiffpair=TRUE checkxsignals=TRUE checkothers=TRUE
MatchedLengths MatchedLengths_LCD_MCU [InNetClass('LCD_MCU')] p8: tolerance=7 checknetsindiffpair=FALSE checkdiffpairvsdiffpair=TRUE checkxsignals=TRUE checkothers=TRUE
MatchedLengths MatchedLengths_JTAG_CN [InNetClass('JTAG_CN')] p9: tolerance=10 checknetsindiffpair=FALSE checkdiffpairvsdiffpair=TRUE checkxsignals=TRUE checkothers=TRUE
MatchedLengths MatchedLengths_OCTOSPI_2 [InNetClass('OCTOSPI_2')] p10: tolerance=7 checknetsindiffpair=FALSE checkdiffpairvsdiffpair=TRUE checkxsignals=TRUE checkothers=TRUE
MatchedLengths MatchedLengths_SRAM_A [InNetClass('SRAM_A')] p11: tolerance=7 checknetsindiffpair=FALSE checkdiffpairvsdiffpair=TRUE checkxsignals=TRUE checkothers=TRUE
MatchedLengths MatchedLengths_JTAG [InNetClass('JTAG')] p12: tolerance=10 checknetsindiffpair=FALSE checkdiffpairvsdiffpair=TRUE checkxsignals=TRUE checkothers=TRUE
MatchedLengths MatchedLengths_USB [InDifferentialPairClass('All Differential Pairs')] p13: tolerance=2.5 checknetsindiffpair=FALSE checkdiffpairvsdiffpair=TRUE checkxsignals=TRUE checkothers=TRUE
MatchedLengths MatchedLengths_SDCARD [InNetClass('SDCARD')] p14: tolerance=14 checknetsindiffpair=FALSE checkdiffpairvsdiffpair=TRUE checkxsignals=TRUE checkothers=TRUE
MatchedLengths MatchedLengths_OCTOSPI_1 [InNetClass('OCTOSPI_1')] p15: tolerance=7 checknetsindiffpair=FALSE checkdiffpairvsdiffpair=TRUE checkxsignals=TRUE checkothers=TRUE
MatchedLengths MatchedLengths_LCD [InNetClass('LCD')] p16: tolerance=7 checknetsindiffpair=FALSE checkdiffpairvsdiffpair=TRUE checkxsignals=TRUE checkothers=TRUE
MinimumSolderMaskSliver [All] p1: minsoldermaskwidth=0
PlaneConnect [All] p1: planeconnectstyle=Relief reliefexpansion=0.508 reliefentries=4 reliefconductorwidth=0.4 reliefairgap=0.4
PolygonConnect PolygonConnect_NO_TH [IsNamedPolygon('NO_TH')] p1: connectstyle=Direct reliefconductorwidth=0.254 reliefentries=4 polygonreliefangle="90 Angle" airgapwidth=0.254
PolygonConnect [All] p2: thpad.connectstyle=Relief thpad.reliefconductorwidth=0.3 thpad.reliefentries=4 thpad.polygonreliefangle="90 Angle" thpad.airgapwidth=0.3 smdpad.connectstyle=Relief smdpad.reliefconductorwidth=0.3 smdpad.reliefentries=4 smdpad.polygonreliefangle="90 Angle" smdpad.airgapwidth=0.3 via.connectstyle=Direct via.reliefconductorwidth=0.4 via.reliefentries=4 via.polygonreliefangle="90 Angle" via.airgapwidth=0.4
RoomDefinition RoomDefinition_4 [InComponentClass('Room Definition 1')] p1: confinementstyle=ConfineIn formatcopy=TRUE lockcomponents=FALSE outline 118.325,74 113.075,74 113.075,94.325 118.325,94.325
RoomDefinition RoomDefinition_3 [InComponentClass('Room Definition 1')] p2: confinementstyle=ConfineIn formatcopy=TRUE lockcomponents=FALSE outline 148.1,129.975 143.525,129.975 143.525,150.3 148.1,150.3
RoomDefinition RoomDefinition_2 [InComponentClass('Room Definition 1')] p3: confinementstyle=ConfineIn formatcopy=TRUE lockcomponents=FALSE outline 35.05,22.525 19.325,22.525 19.325,42.05 35.05,42.05
RoomDefinition RoomDefinition_1 [InComponentClass('Room Definition 1')] p4: confinementstyle=ConfineIn formatcopy=TRUE lockcomponents=FALSE outline 84.675,84.85 71.225,84.85 71.225,96.625 84.675,96.625
RoomDefinition [InComponentClass('Room Definition 1') vs False] p5: confinementstyle=ConfineIn formatcopy=TRUE lockcomponents=FALSE outline 66.725,136.85 86.825,136.85 86.825,118.8 66.725,118.8
RoutingPriority RoutingPriority_ALL [All] p1: routingpriority=1
RoutingVias [All] p1: holewidth=0.2 width=0.45 viastyle="Through Hole" minholewidth=0.1 minwidth=0.25 maxholewidth=0.2 maxwidth=0.45
SilkToSilkClearance [All] p1: silktosilkclearance=0
SilkToSolderMaskClearance [IsPad] p1: minsilkscreentomaskgap=0 clearancetoexposedcopper=TRUE
SolderMaskExpansion SolderMaskExpansion_Vias [InPadClass('All Pads')] p1: expansion=0.102 istentingtop=FALSE
SolderMaskExpansion [All] p2: expansion=0.102 istentingtop=FALSE
Width Width_BGA_MCU [WithinRoom('RoomDefinition')and TouchesRoom('RoomDefinition')] p1: maxlimit=0.25 minlimit=0.08 preferedwidth=0.1
Width Width_BGA_SRAM [WithinRoom('RoomDefinition_1')and TouchesRoom('RoomDefinition_1')] p2: maxlimit=0.25 minlimit=0.09 preferedwidth=0.1
Width Width_BGA_STLINK [WithinRoom('RoomDefinition_2')and TouchesRoom('RoomDefinition_2')] p3: maxlimit=0.25 minlimit=0.09 preferedwidth=0.1
Width Width_CONN [WithinRoom('RoomDefinition_3','RoomDefinition_4')and TouchesRoom('RoomDefinition_3','RoomDefinition_4')] p4: maxlimit=0.25 minlimit=0.1 preferedwidth=0.1
Width Width_100mA [InNetClass('100mA')] p5: maxlimit=1 minlimit=0.2 preferedwidth=0.2 minimp=50.000000 maximp=50.000000 favimp=50.000000
Width Width_150mA [InNetClass('150mA')] p6: maxlimit=1 minlimit=0.2 preferedwidth=0.2 minimp=50.000000 maximp=50.000000 favimp=50.000000
Width Width_200mA [InNetClass('200mA')] p7: maxlimit=1 minlimit=0.25 preferedwidth=0.3 minimp=50.000000 maximp=50.000000 favimp=50.000000
Width Width_500mA [InNetClass('500mA')] p8: maxlimit=1 minlimit=0.25 preferedwidth=0.8
Width Width_1A [InNetClass('1A')] p9: maxlimit=3 minlimit=0.25 preferedwidth=2
Width "Width 50 ohms" [InNetClass('50 Ohms')] p10: maxlimit=0.3 minlimit=0.09 preferedwidth=0.3 toplayer_minwidth=0.1 toplayer_maxwidth=0.1 toplayer_prefwidth=0.1 midlayer1_minwidth=0.127 midlayer1_maxwidth=0.127 midlayer1_prefwidth=0.127 midlayer2_maxwidth=0.09 midlayer2_prefwidth=0.09 midlayer3_minwidth=0.3 midlayer4_minwidth=0.127 midlayer4_maxwidth=0.127 midlayer4_prefwidth=0.127 bottomlayer_minwidth=0.1 bottomlayer_maxwidth=0.1 bottomlayer_prefwidth=0.1 minimp=50.000000 maximp=50.000000 favimp=50.000000
Width Width_1 [All] p11: maxlimit=1 minlimit=0.09 preferedwidth=0.12 toplayer_minwidth=0.1 midlayer1_minwidth=0.1 midlayer3_minwidth=0.1 midlayer4_minwidth=0.1 bottomlayer_minwidth=0.1 minimp=50.000000 maximp=50.000000 favimp=50.000000
16 further rules are at their usual default settings.

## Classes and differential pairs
net class LCD: D0 D1 D2 D3 D4 D5 D6 D7 D8 D9 D10 D11 D12 D13 D14 D15 FMC_A22_LCD_RS FMC_NOE FMC_NWE
component class U_MOTOR_CONTROL: C2 C5 C8 C14 C20 C21 C24 C28 C50 C59 C62 C66 C67 C130 C133 CN12 HW53 HW54 R110 R113 R123 R227 R241 SB3
component class U_MCU_IO: R8 R16 R17 R37 R41 R58 R65 R68 R70 R79 R82 R115 R123 R126 R128 R132 R133 R140 R141 R146 R149 R152 R155 R156 R159 R161 R164 R166 R167 R169 R172 R174 R175 R176 R178 R182 R183 R184 R185 R187 R189 R191 R192 R193 R194 R198 R199 R203 R204 R205 R206 R208 R209 R210 R212 R213 R214 R215 R216 R217 R221 R224 R227 R229 R230 R232 R234 R244 SB3 SB7 SB9 SB11 SB12 SB14 SB15 SB16 SB20 SB24 SB25 SB28 SB29 SB36 SB37 SB38 SB42 SB43 SB45 SB48 SB50 SB51 SB55 SB57 SB59 SB61 SB63 SB67 SB69 SB70 SB72 SB74 SB77 SB79 SB80 SB84 SB87 SB90 SB91 SB97 SB99 SB102 SB109 SB110 SB111 SB112 SB115 SB117 SB119 SB123 SB124 SB125 SB127 SB128 SB130 SB131 SB133 SB137 SB138 SB139 SB142 SB145 SB146 TP15 TP37 U8
component class U_LCD_TFT_320x240: C22 C78 C113 CN14 H1 H2 L3 L4 Q9 R16 R70 R83 R106 R115 R184 SB38 SB99 SB102 SB124
component class U_PERIPHERAL: B2 C21 C93 C124 CN27 HW27 HW28 HW31 HW32 HW34 HW35 HW36 HW37 HW38 HW39 HW41 HW42 HW43 HW44 JP11 JP16 LD2 LD3 LD4 LD8 R11 R16 R17 R37 R56 R79 R83 R113 R123 R126 R140 R174 R199 RV1 RV2 TP15 TP21 U12
component class U_SDCARD: C113 C148 CN27 R110 R115 R140 R152 R161 R227 SB79 U22 U39
component class U_AUDIO: C2 C8 C21 C22 C24 C28 C50 C59 C62 C63 C66 C67 C68 C76 C84 C93 C102 C107 C161 CN14 CN31 JP16 R16 R37 R83 R112 R123 R128 R155 SB38 SB125 TP15 TP35 U12 U15 U28 U39
component class U_MFX_IO_IDD_measurement: C2 C5 C8 C22 C28 C98 C113 C124 C130 C131 C155 C158 C171 C181 CN27 CN31 D7 HW51 HW52 JP16 R15 R16 R19 R70 R106 R110 R114 R123 R167 R169 R184 R210 R239 R241 SB112 TP19 U8 U38 U39
component class U_BOARD_PWR: C5 C8 C22 C24 C28 C59 C66 C98 C113 C133 C158 CN31 HW55 JP11 LD2 R8 R17 R106 R112 R126 R156 R241 RV1 SB3 SB99 SB145 TP21 TP29 TP34 TP35 TP37 U24 U28 U39
component class U_MCU_PWR: C17 C22 C28 C93 C98 C105 C110 C113 C115 C118 C120 C121 C124 C125 C130 C131 C135 C136 C138 C143 C147 C148 C151 C155 C158 C171 CN14 JP2 JP8 JP11 JP17 JP28 JP29 JP34 SB117 TP1 TP15 TP21 TP24 TP34 TP35 TP36
differential pair class 100Ohms_Diff: OCTOSPI_CLK OCTOSPI_CLK_MCU
differential pair class 90Ohms_Diff: PA11/PA12 STLINK_USB_D USB_DEV_HS USB_DEV_HS_CN USB_FS USB_FS1
component class U_Extension_Connector: CN14 CN15 CN20 CN27 R156
component class U_FDCAN_RS232: C8 C22 C28 C59 C93 C113 C124 C131 C143 CN19 CN27 JP8 JP11 JP36 R16 R38 R65 R123 R128 R155 R167 SB3 SB109 U8 U22 U38 U39
component class U_JTAG_TRACE: CN12 CN14 CN19 CN27 R16 R31 R41 R110 R112 R115 R123 R128 R135 R140 R152 R155 R161 R210 R224 R232 R239 R241 U8 U12 U28 U32 U38 U39 U42
component class U_MCU_CLOCK_&_RESET: B1 B2 B4 C17 C28 C67 C99 C121 C124 C155 D3 D7 JP8 JP11 JP16 R16 R58 R70 R115 R126 R128 R152 R230 R232 SB14 SB29 SB102 SB112 SB117 SB119 SW2 U8 U22 U39 X2 X3
component class U_Mechanical_Parts: H1 H3 H4 H5
component class U_OCTOSPI: C24 C113 C148 C155 C158 C181 R83 R152 R169 R210 SB112 SB125 TP21 U8 U39
component class U_PMOD_STMOD+: C2 R16 R58 R65 R115 R123 R126 SW2 U8
component class U_SMARTCARD: C8 C59 C66 C113 C124 C148 C161 CN14 D7 R8 R16 R83 R106 R114 R115 R152 R161 R167 R210 SB91 SB124 TP36 TP37 U39 U42
component class U_SRAM: C8 C67 C113 R128 R155 R192 SB119 U12
component class U_STLINK_V2: C8 C21 C28 C35 C59 C67 C98 C113 C124 C130 C131 C148 C155 C158 C161 C171 C181 CN14 CN15 CN31 D4 D5 D6 D7 HW17 JP8 LD4 LD8 Q3 R8 R16 R17 R19 R22 R58 R68 R70 R77 R110 R114 R115 R123 R126 R152 R161 R169 R227 TP36 U12 U22 U28 U39 U42 X3
component class U_USB_TYPEC: C8 CN27 LD4 Q1 R8 R83 R106 R126 R184 SB124 U8 U22
net class OCTOSPI_1: OCTOSPI_1_CLK_N OCTOSPI_1_CLK_P OCTOSPI_1_DQS OCTOSPI_1_IO0 OCTOSPI_1_IO1 OCTOSPI_1_IO2 OCTOSPI_1_IO3 OCTOSPI_1_IO4 OCTOSPI_1_IO5 OCTOSPI_1_IO6 OCTOSPI_1_IO7
net class OCTOSPI_2: OCTOSPI_2_CLK OCTOSPI_2_DQS OCTOSPI_2_IO0 OCTOSPI_2_IO1 OCTOSPI_2_IO2 OCTOSPI_2_IO3 OCTOSPI_2_IO4 OCTOSPI_2_IO5 OCTOSPI_2_IO6 OCTOSPI_2_IO7
net class SRAM_A: A0 A1 A2 A3 A4 A5 A6 A7 A8 A9 A10 A11 A12 A13 A14 A15 A16 A17 A18 A19 A20 FMC_NBL0 FMC_NBL1
net class SDCARD: SDIO1_CLK SDIO1_CMD SDIO1_D0 SDIO1_D1 SDIO1_D2 SDIO1_D3
net class SRAM_A_MCU: PD11 PD12 PD13 PE0 PE1 PE3 PE4 PF0 PF1 PF2 PF3 PF4 PF5 PF12 PF13 PF14 PF15 PG0 PG1 PG2 PG3 PG4 PG5
net class SDCARD_MCU: PC8 PC9 PC10 PC11 PC12 PD2
net class LCD_MCU: PD0 PD1 PD4 PD5 PD8 PD9 PD10 PD14 PD15 PE6 PE7 PE8 PE9 PE10 PE11 PE12 PE13 PE14 PE15
net class OCTOSPI_1_MCU: PA3 PA6 PA7 PB0 PB1 PB2 PB12 PC0 PC1 PC2 PC3
net class OCTOSPI_2_MCU: DCMI_D0 DCMI_D1 DCMI_D2 DCMI_D3 PH4 PH6 PH8 PI1 PI2 PI3
net class JTAG_MCU: PA13 PA14 PA15 PB3
net class Camera: DCMI_D0 DCMI_D1 DCMI_D2 DCMI_D3 DCMI_D4 DCMI_D5 DCMI_D6 DCMI_D7 DCMI_PIXCLK PH5 PH8 PI5
differential pair USB_FS: +USB_FS_P -USB_FS_N
differential pair OCTOSPI_CLK: +OCTOSPI_1_CLK_P -OCTOSPI_1_CLK_N
differential pair USB_DEV_HS_CN: +USB_DEV_HS_CN_P -USB_DEV_HS_CN_N
differential pair USB_DEV_HS: +USB_DEV_HS_P -USB_DEV_HS_N
differential pair PA11/PA12: +PA12 -PA11
differential pair OCTOSPI_CLK_MCU: +PA3 -PB12

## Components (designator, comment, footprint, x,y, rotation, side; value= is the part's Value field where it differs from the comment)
B1 "" SWI_XIEJIA_MT-008A_6P 89.257,6.243 r45 top value=MT-008A
B2 "" SWI_WEALTHMETAL_TD-0341_4P_BLACK 32.6,6.4 r270 top value=SW_BLACK
B3 "" SWI_WEALTHMETAL_TD-0341_4P_BLUE 55.8,6.391 r90 top value=SW_BLUE
B4 "" SWI_WEALTHMETAL_TD-0341_4P_BLUE 72.1,6.391 r90 top value=SW_BLUE
C1 "Capacitor" C0603 117.35,160.4 r270 top value=1uF
C2 "" C0402 68.2,159.75 r90 top value=1nF
C3 "" C0402 81.7,159.725 r90 top value=100nF
C4 "" C0402 84.2,159.725 r270 top value=100nF
C5 "" C0402 64.1,159.7 r90 top value=100nF
C6 "" C0402 61.4,159.7 r270 top value=100nF
C7 "" C0402 62.6,159.7 r90 top value=100nF
C8 "" C0402 66.9,159.7 r270 top value=100nF
C9 "" C0402 71.1,159.7 r270 top value=100nF
C10 "" C0402 101.65,159.65 r270 top value=1nF
C11 "" C0402 86.7,157 r270 top value=100nF
C12 "" C0402 72.4,156.95 r90 top value=100nF
C13 "" C0402 73.9,156.95 r90 top value=100nF
C14 "" C0402 75.4,156.95 r90 top value=100nF
C15 "" C0402 89.8,156.9 r90 top value=100nF
C16 "" C0402 65.7,156.8 r90 top value=10nF
C17 "" C0603 37.025,156.825 r0 top value="100nF, 50V"
C18 "" C0402 42.4,154.2 r90 top value=10pF
C19 "" C0603 53.55,150.875 r270 top value=100nF
C20 "" C1206_H0P85 74.05,139.25 r180 top value=39nF
C21 "Capacitor" C0402 80.475,138.65 r0 top value=390nF
C22 "" C0402 86.83,129.977 r270 top value=2.2uF
C23 "" C0402 85.655,129.977 r270 top value=2.2uF
C24 "" C0402 88.7,127.625 r0 top value=100pF
C25 "" C0402 24.55,119.575 r270 top value=100nF
C26 "" C0402 21.05,117.5 r0 top value=100nF
C27 "" C0603 20.725,116.35 r0 top value=4.7uF
C28 "Capacitor" C0402 77.775,114.625 r0 top value=3.9pF
C29 "Capacitor" C0402 79.675,114.625 r0 top value=3.9pF
C30 "Capacitor" C0402 72.675,114.6 r180 top value=3.9pF
C31 "Capacitor" C0402 74.775,114.6 r0 top value=3.9pF
C32 "" C0402 19.275,107.375 r0 top value=100nF
C33 "" C0603 126.55,101.925 r0 top value=1uF
C34 "Capacitor" C0402 121.35,101.925 r180 top value=10uF
C35 "" C0603 79.15,97.3 r180 top value=4.7uF
C36 "" C0402 79.15,96.15 r180 top value=100nF
C37 "" C0402 119.05,93.975 r90 top value=100nF
C38 "" C0402 112.35,93.95 r90 top value=100nF
C39 "" C0603 32.4,91.9 r180 top value=1uF
C40 "" C0402 35.5,91 r180 top value=100nF
C41 "" C0402 40,90.4 r270 top value=100nF
C42 "" C0402 32.2,90.7 r180 top value=100nF
C43 "" C0402 78.15,85.625 r0 top value=100nF
C44 "" C0402 30.2,81.1 r270 top value=100nF
C45 "" C0402 39,77.45 r0 top value=100nF
C46 "" C0603 15.8,74.9 r90 top value=4.7uF
C47 "" C0603 20.8,74.9 r90 top value=4.7uF
C48 "" C0603 43.9,73.8 r90 top value=4.7uF
C49 "" C0603 48.9,73.8 r90 top value=4.7uF
C50 "" C0402 17.9,72.4 r0 top value=100nF
C51 "" C0402 46,71.3 r0 top value=100nF
C52 "" C0402 80.6,56.6 r90 top value=100nF
C53 "" C0402 83.1,56.1 r180 top value=100nF
C54 "" C0402 24.6,55.125 r270 top value=1uF
C55 "" C0402 36.075,54.55 r180 top value=1uF
C56 "" C0402 42.675,54.55 r180 top value=100nF
C57 "" C0402 36.075,53.6 r0 top value=100nF
C58 "" C0402 42.675,53.6 r0 top value=1uF
C59 "" C0402 123.55,52.275 r90 top value=100nF
C60 "" CPOL_TAJ-C_2312_H2P6 15.699,44.653 r270 top value=220uF
C61 "" C0402 25.95,51.525 r270 top value=1uF
C62 "Capacitor" C0402 42.675,51.7 r180 top value=10nF
C63 "" C0402 128.15,48.675 r180 top value=100nF
C64 "" C0402 13.164,45.792 r270 top value=100nF
C65 "" C0603 119.8,45.2 r90 top value=150pF
C66 "" C0603 125,45.2 r270 top value=1uF
C67 "" C0603 121.1,45.2 r90 top value=150pF
C68 "" C0402 122.4,44.9 r90 top value=100nF
C69 "Capacitor" C0402 126.5,43.2 r180 top value=10uF
C70 "" C0402 81.2,42.6 r0 top value=100nF
C71 "" C0402 75.5,41.9 r270 top value=100nF
C72 "" C0603 126.5,41.8 r180 top value=1uF
C73 "" C0603 81.2,41.3 r180 top value=4.7uF
C74 "" C0402 116.8,41.4 r0 top value=100nF
C75 "" C0402 28.575,40.5 r270 top value=100nF
C76 "" C0603 126.5,40.4 r180 top value=1uF
C77 "" C0603 115.8,39.7 r90 top value=1uF
C78 "" C0402 117.2,40 r270 top value=100nF
C79 "" C0402 125.7,38.9 r90 top value=100nF
C80 "" C0603 127.4,38.6 r180 top value=1uF
C81 "" C0603 33.25,37.95 r270 top value=4.7uF
C82 "" C0402 32.1,37.95 r90 top value=1uF
C83 "" C0402 26.1,37.625 r90 top value=100nF
C84 "" C0603 126.5,37.3 r180 top value=22nF
C85 "" C0603 134.2,35.5 r270 top value=1uF
C86 "" C0603 126.5,35.9 r180 top value=22nF
C87 "" C0603 142.2,35.1 r90 top value=1uF
C88 "" C0603 123.2,34 r270 top value=1uF
C89 "" C0603 124.6,34 r90 top value=1uF
C90 "" C0402 122,34.3 r270 top value=100nF
C91 "" C0603 137.9,33.3 r270 top value=4.7uF
C92 "" C0805 111.5,31.1 r270 top value=10uF
C93 "" C0402 110,31.1 r270 top value=100nF
C94 "" C0402 39.375,30.975 r0 top value=100nF
C95 "" C0402 41.575,30.975 r0 top value=100nF
C96 "" C0603 124.4,29 r270 top value=1uF
C97 "" C0402 126.4,29 r270 top value=10nF
C98 "" C0402 135.8,27.9 r270 top value=100nF
C99 "" C0603 131.8,27.5 r90 top value=1uF
C100 "" C0603 139.6,27.5 r90 top value=1uF
C101 "" C0603 133.8,27.7 r0 top value=1uF
C102 "" C0603 141.8,27.7 r0 top value=1uF
C103 "" C0402 143.8,27.7 r0 top value=100nF
C104 "" C0402 39.375,26.775 r0 top value=100nF
C105 "" C0402 41.575,26.775 r0 top value=100nF
C106 "" C0603 25.575,24.275 r90 top value=2.2uF
C107 "Capacitor" C0402 7.45,24.15 r270 top value=100pF
C108 "" C0402 30.875,23.3 r180 top value=20pF
C109 "" C0603 124.7,22.7 r180 top value=1uF
C110 "" C0402 114.775,21 r270 top value=100nF
C111 "" C0402 46.2,8.675 r90 top value=100nF
C112 "Capacitor" C0402 34.28,158.763 r0 bottom value=330pF
C113 "Capacitor" C0402 35.234,157.456 r270 bottom value=330pF
C114 "" C0603 32.9,154.675 r90 bottom value=100nF
C115 "" C0603 28.375,151.525 r180 bottom value=100nF
C116 "" C0603 38.425,148.8 r0 bottom value="100nF, 50V"
C117 "" C0603 97.525,143.6 r270 bottom value=100nF
C118 "" C0603 79.725,133.175 r270 bottom value=4.7uF
C119 "" C0402 78,133.425 r270 bottom value=100nF
C120 "" C0402 77.1,133.425 r270 bottom value=100nF
C121 "" C0402 75.975,133.425 r270 bottom value=100nF
C122 "" C0402 75.025,133.425 r270 bottom value=100nF
C123 "" C0402 71.35,131.2 r0 bottom value=100nF
C124 "" C0402 80.022,130.074 r90 bottom value=100nF
C125 "" C0402 18.25,130 r0 bottom value=100nF
C126 "" C0402 30.05,129.475 r270 bottom value=100nF
C127 "" C0402 18.25,129.075 r0 bottom value=100nF
C128 "Capacitor" C0402 87.913,128.187 r270 bottom value=10uF
C129 "" C0402 87.013,128.187 r270 bottom value=100nF
C130 "Capacitor" C0402 88.763,128.187 r270 bottom value=10uF
C131 "" C0402 71.45,128.5 r0 bottom value=100nF
C132 "" C0402 30.35,128.075 r180 bottom value=100nF
C133 "" C0402 18.25,128.075 r180 bottom value=100nF
C134 "" C0402 82.675,128 r180 bottom value=100nF
C135 "" C0402 71.45,127.45 r0 bottom value=100nF
C136 "" C0402 81.577,126.293 r270 bottom value=100nF
C137 "" C0402 71.45,126.575 r0 bottom value=2.2uF
C138 "" C0402 71.45,125.65 r0 bottom value=2.2uF
C139 "" C0402 71.45,124.725 r0 bottom value=100nF
C140 "" C0402 80.475,122.2 r90 bottom value=100nF
C141 "" C0402 79.35,122.2 r90 bottom value=100nF
C142 "" C0402 77,122.2 r90 bottom value=100nF
C143 "" C0402 74.5,122.2 r90 bottom value=100nF
C144 "Capacitor" C0402 73.575,122.2 r90 bottom value=10uF
C145 "" C0603 75.625,121.875 r270 bottom value=1uF
C146 "" C0402 74.5,120.5 r270 bottom value=100nF
C147 "" C0402 77.275,120 r270 bottom value=100nF
C148 "" C0603 80.5,119.575 r270 bottom value=1uF
C149 "" C0603 79.125,119.575 r270 bottom value=1uF
C150 "" C0603 135.9,118.7 r270 bottom value=22uF
C151 "" C0402 24.65,119.175 r0 bottom value=100nF
C152 "" C0402 137.25,118.725 r90 bottom value=100nF
C153 "" C0402 24.6,115.575 r180 bottom value=100nF
C154 "" C0402 128.825,102.125 r180 bottom value=100nF
C155 "" C0402 122.9,99.275 r270 bottom value=100nF
C156 "" C0402 131.5,96.825 r180 bottom value=100nF
C157 "" C0603 43.55,86.9 r90 bottom value=4.7uF
C158 "" C0402 42.25,87.2 r270 bottom value=100nF
C159 "" C0402 84.5,51.6 r0 bottom value=100nF
C160 "" C0603 84.5,50.3 r180 bottom value=4.7uF
C161 "" C0402 22.85,36.725 r0 bottom value=100nF
C162 "" C0402 31.05,35.55 r270 bottom value=100nF
C163 "" C0402 29.05,35.025 r90 bottom value=100nF
C164 "" C0402 27.1,35.025 r90 bottom value=100nF
C165 "" C0402 22.85,35.325 r0 bottom value=100nF
C166 "" C0402 31.575,33.4 r0 bottom value=100nF
C167 "" C0402 25.125,32.9 r270 bottom value=100nF
C168 "" C0402 31.575,32.1 r0 bottom value=100nF
C169 "" C0402 23.5,31.375 r0 bottom value=100nF
C170 "" C0402 30,30.8 r180 bottom value=100nF
C171 "" C0402 24.754,30.298 r270 bottom value=2.2uF
C172 "" C0402 22.1,30.15 r180 bottom value=100nF
C173 "" C0402 30,29.55 r180 bottom value=100nF
C174 "" C0402 22.1,29.3 r180 bottom value=100nF
C175 "" C0402 25.075,28.65 r90 bottom value=100nF
C176 "" C0402 26.425,28.1 r90 bottom value=100nF
C177 "" C0402 29.493,27.87 r270 bottom value=2.2uF
C178 "" C0402 28.175,26.85 r0 bottom value=100nF
C179 "" C0402 25.325,26.825 r180 bottom value=100nF
C180 "" C0603 129.3,16.5 r90 bottom value=1uF
C181 "" C0603 112.575,9.1 r180 bottom value=1uF
C182 "Capacitor" C0402 12.524,40.533 r90 top value=10pF
C183 "Capacitor" C0402 11.691,40.534 r90 top value=10nF
C184 "Capacitor" C0603 8.968,40.863 r90 top value=4.7uF
C185 "Capacitor" C0603 3.266,44.94 r0 top value=4.7uF
C186 "Capacitor" C0402 3.268,46.043 r0 top value=10nF
C187 "Capacitor" C0402 3.273,46.873 r0 top value=10pF
C188 "" C0603 10.274,45.754 r90 top value=1uF
C189 "Capacitor" C0402 3.276,49.817 r0 top value=10nF
CN1 "USB_TYPE_C_Receptacle_317JD24BZTF3K3C3" CON_USB-TYPEC_COXOC_317JD24BZTF3K3C3 46.59,170.65 r180 top value=317JD24BZTF3K3C3
CN2 "" CON_SAMTEC_TST-117-01-T-D 82.902,166.37 r180 top locked value="Header 17x2 IDC34 MotorControl"
CN3 "Socket 6X2 PMOD" CON_SAMTEC_SSW-106-02-F-D-RA__PMOD 136.45,159.091 r180 top
CN4 "" CON_SAMTEC_SSM-104-L-DH 7.95,162.375 r180 top value=SSM-104-L-DH
CN5 "" CON_SAMTEC_ERF8-010-050-S-DV-TR 130.65,150.275 r0 top value=ERF8-010-05.0-S-DV-TR
CN6 "DB9_Header_male_2301843-2" CON_DB9-MALE_TYCO_2301843-2 4.2,137.1 r270 top value=DB9_Male_2301843-2
CN7 "Socket 10X2 STMod+" CON_SAMTEC_SQT-110-01-F-D-RA__STMOD+ 145.8,140.128 r90 top
CN8 "" CON_SAMTEC_TSW-102-07-G-S 97.675,146.6 r180 top value="Header 2x1"
CN9 "Header 25x2" CON_SAMTEC_FTR-125-03-L-D-LC 43.493,129.765 r270 top
CN10 "Header 25x2" CON_SAMTEC_FTR-125-03-L-D-LC 112.073,129.765 r270 top
CN11 "" CON_SAMTEC_ERF8-010-050-S-DV-TR 130.65,124.275 r0 top value=ERF8-010-05.0-S-DV-TR
CN12 "" CON_SAMTEC_FTSH-110-01-L-DV 149.925,112.325 r90 top value="Header 10x2"
CN13 "" CON_TAG-C_TC2050-IDC-NL 133.975,103.725 r90 top value=TC2050-IDC-NL
CN14 "Header 17x2" CON_SAMTEC_FTR-117-03-L-D-LC 53.475,94.33 r270 top
CN15 "Header 17x2" CON_SAMTEC_FTR-117-03-L-D-LC 102.091,94.33 r270 top
CN16 "" CON_SAMTEC_CLM-120-02-L-D_Reverse-to-Camera 115.675,84.155 r180 top value=CLM-120-02-L-D
CN17 "" CON_CVILUX_CH87-20-2-V-1-00 150.03,86.39 r270 top value=TST-110-01-G-D
CN18 "" CON_STDC14_Receiver_MEDIUM_WITH_MIPI10_3D 134.05,89.225 r90 top value="MIPI10 on STDC14 footprint"
CN19 "" CON_SAMTEC_TSW-104-07-G-S 8.139,86.411 r0 top value="Header 4x1"
CN20 "" CON_SAMTEC_TSW-102-07-G-S 18.57,86.4 r0 top value="Header 2x1"
CN21 "" BAT_HARWIN_S8411-45R_SMD_2P 78.083,69 r180 top value="CR1220 holder"
CN22 "DB9_Header_male_2301843-2" CON_DB9-MALE_TYCO_2301843-2 150.6,52.1 r90 top value=DB9_Male_2301843-2
CN23 "" CON_SAMTEC_SSW-117-21-X-D_INV 105.23,40.86 r90 top value=TFT_LCD_MB989_SOCKET
CN24 "" CON_SAMTEC_TSW-103-07-F-S 134.6,40.2 r180 top value="Header 3x1"
CN25 "" CON_DC-POWER-SOCKET_CLIFF_FC68149_DC10B 0.025,34.7 r180 top value=DC10B
CN26 "USB_uB_105017.0001" CON_USBMICROB_MOLEX_105017-0001_H2P90 0,21.075 r270 top value=USB_uB_105017-0001
CN27 "" CON_PHONE-JACK-3P5_HY_PJ3028B 154.8,22 r180 top value=PJ3028B-3_4P
CN28 "Header 4x1" CON_SAMTEC_TSW-104-07-G-S 16.35,17.6 r180 top
CN29 "" CON_FCI_20021311-XXX20XXLF 145.7,7.6 r180 top value=20021311-00020T4LF
CN30 "" CON_MICROSD_YAMAICHI_PJS008-2003-1 154.798,120.587 r0 bottom value=PJS008-2003-1
CN31 "" CON_CARD-SOCKET_GUANG-LIAN-WEI_2480-208-503-100-RC 77.13,18.3 r270 bottom value=2480-208-503-100-RC
D1 "" DIO_SOD323 35.55,162.025 r0 top value=BAT60JFILM
D2 "" DIO_SOD523_1A_2K 37.05,158.225 r180 top value=BAT54KFILM
D3 "" DIO_SOD323 34.3,93.8 r180 top value=BAT60JFILM
D4 "BAT60JFILM" DIO_SOD323 35.4,62 r0 top
D5 "BAT60JFILM" DIO_SOD323 35.396,59.996 r0 top
D6 "BAT60JFILM" DIO_SOD323 35.4,58 r0 top
D7 "BAT60JFILM" DIO_SOD323 35.395,55.989 r0 top
D8 "EMIF03-SIM02M8" ESD_UQFN8-EPAD_1P7X1P5_P040 81.8,35.6 r270 top
D9 "" DIO_SOD323 34.2,14.9 r0 top value=BAT60JFILM
F1 "FUSE" PTC_Panasonic_micro_chip_fuse_0402 7.599,45.625 r0 top value=ERBRD2R00X
H1 "" PTH_M1261-3005-N_3P5X6_M3_H14 27.812,64.353 r0 top
H2 "" PTH_M1261-3005-N_3P5X6_M3_H14 27.785,17.363 r0 top
H3 "" PTH_M1261-3005-N_3P5X6_M3_H14 124.177,166.37 r180 bottom locked
H4 "" PTH_M1261-3005-N_3P5X6_M3_H14 21.307,166.37 r180 bottom locked
H5 "" PTH_M1261-3005-N_3P5X6_M3_H14 124.177,5.08 r180 bottom locked
H6 "" PTH_M1261-3005-N_3P5X6_M3_H14 21.307,5.08 r180 bottom locked
HW100 "STICKER_BOARD" STICKER_BOARD_25X9 62.331,59.062 r180 bottom value="Sticker board"
HW101 "STICKER_PRODUCT" STICKER_PRODUCT_25X9 62.291,46.622 r180 bottom value="Sticker product"
JP1 "Jumper_Header 2x1" CON_SAMTEC_TSW-102-07-G-S 28.15,166.825 r90 top value="Shunt not fitted"
JP2 "Jumper_Header 2x1" CON_SAMTEC_TSW-102-07-G-S 118.275,166.475 r90 top value="Shunt not fitted"
JP3 "" CON_SAMTEC_TSW-102-07-G-S 35.6,164.875 r0 top value="Shunt not fitted"
JP4 "" CON_SAMTEC_TSW-102-07-G-S 62.7,150.945 r0 top value="Shunt Fitted"
JP5 "" CON_SAMTEC_TSW-102-07-G-S 62.7,147.55 r0 top value="Shunt Fitted"
JP6 "" CON_SAMTEC_TSW-102-07-G-S 18.675,143.325 r90 top value="Shunt Fitted"
JP7 "Jumper_Header 2x1" CON_SAMTEC_TSW-102-07-G-S 21.85,143.325 r90 top value="Shunt not fitted"
JP8 "" CON_SAMTEC_TSW-102-07-G-S 25.05,143.325 r90 top value="Shunt Fitted"
JP9 "Jumper_Header 2x1" CON_SAMTEC_TSW-102-07-G-S 91.74,140.325 r0 top value="Shunt not fitted"
JP10 "" CON_SAMTEC_TSW-103-07-F-S 19.325,134.66 r270 top value="Shunt Fitted 1-2"
JP11 "" CON_SAMTEC_TSW-103-07-F-S 23.7,134.66 r270 top value="Shunt Fitted 1-2"
JP12 "Jumper_Header 2x1" CON_SAMTEC_TSW-102-07-G-S 91.74,136.925 r0 top value="Shunt not fitted"
JP13 "Jumper_Header 2x1" CON_SAMTEC_TSW-102-07-G-S 55.775,136.475 r0 top value="Shunt not fitted"
JP14 "" CON_SAMTEC_TSW-102-07-G-S 29.45,136.26 r180 top value="Shunt Fitted"
JP15 "Jumper_Header 2x1" CON_SAMTEC_TSW-102-07-G-S 29.45,133.035 r180 top value="Shunt not fitted"
JP16 "" CON_SAMTEC_TSW-102-07-G-S 93.525,130.055 r270 top value="Shunt Fitted"
JP17 "" CON_SAMTEC_TSW-103-07-F-S 99.34,111.96 r90 top value="Shunt Fitted 1-2"
JP18 "" CON_SAMTEC_TSW-102-07-G-S 95.609,110.87 r270 top value="Shunt Fitted"
JP19 "" CON_SAMTEC_TSW-102-07-G-S 39.575,110.225 r0 top value="Shunt Fitted"
JP20 "" CON_SAMTEC_TSW-103-07-F-S 121.45,108.325 r0 top value="Shunt Fitted 1-2"
JP21 "" CON_SAMTEC_TSW-103-07-F-S 9.2,104.36 r270 top value="Shunt Fitted 1-2"
JP22 "Jumper_Header 3x1 Fitted 2-3" CON_SAMTEC_TSW-103-07-F-S 14,104.3 r270 top value="Shunt Fitted 2-3"
JP23 "" CON_SAMTEC_TSW-103-07-F-S 38.3,105.95 r0 top value="Shunt Fitted 1-2"
JP24 "" CON_SAMTEC_TSW-103-07-F-S 63.4,73.125 r270 top value="Shunt Fitted 1-2"
JP25 "" CON_SAMTEC_TSW-105-07-X-D 8.139,61.16 r90 top value="Shunt Fitted 1-2"
JP26 "" CON_SAMTEC_TSW-103-07-F-S 119.3,57.05 r180 top value="Shunt Fitted 1-2"
JP27 "" CON_SAMTEC_TSW-102-07-G-S 117.35,52.4 r90 top value="Shunt not fitted"
JP28 "" CON_SAMTEC_TSW-102-07-G-S 135.15,52.045 r270 top value="Shunt not fitted"
JP29 "" CON_SAMTEC_TSW-102-07-G-S 117.35,46.6 r90 top value="Shunt not fitted"
JP30 "Jumper_Header 2x1" CON_SAMTEC_TSW-102-07-G-S 149.45,31.95 r270 top value="Shunt not fitted"
JP31 "Jumper_Header 2x1" CON_SAMTEC_TSW-102-07-G-S 152.675,31.95 r270 top value="Shunt not fitted"
JP32 "Jumper_Header 2x1" CON_SAMTEC_TSW-102-07-G-S 16.2,21.9 r180 top value="Shunt not fitted"
JP33 "Jumper_Header 2x1" CON_SAMTEC_TSW-102-07-G-S 19.125,12.05 r90 top value="Shunt not fitted"
JP34 "" CON_SAMTEC_TSW-102-07-G-S 34.3,12.1 r180 top value="Shunt not fitted"
JP35 "" CON_SAMTEC_TSW-103-07-F-S 43.9,6.6 r270 top value="Shunt Fitted 1-2"
JP36 "Jumper_Header 2x1" CON_SAMTEC_TSW-102-07-G-S 118.625,5 r90 top value="Shunt not fitted"
L1 "Inductor" L0805_H0P9 88.725,129.6 r270 top value=2.2uH
L3 "" L0603 114,31.9 r180 top value=600R@100MHz
L4 "" L0603 114,30.3 r180 top value=600R@100MHz
LD1 "" LED_0603_OSRAM_LG-Q396-PS-35_GREEN_1A2K_H0P4 53.7,164.2 r270 top value=GREEN
LD2 "" LED_0603_OSRAM_LG-Q396-PS-35_GREEN_1A2K_H0P4 13,68.7 r0 top value=GREEN
LD3 "" LED_0603_VISHAY_VLMS1300-GS08_RED_1A2K_H0P8 23,52.025 r270 top value=RED
LD4 "LD_BICOLOR_CMS" LED_BI-GR_HSMF-A201-A00J1 3.9,6.8 r0 top
LD5 "" LED_0603_OSRAM_LG-Q396-PS-35_GREEN_1A2K_H0P4 7.25,5.2 r270 top value=GREEN
LD6 "" LED_0603_VISHAY_VLMS1300-GS08_RED_1A2K_H0P8 9.15,5.2 r270 top value=RED
LD7 "" LED_0603_SMD-B_BLUE_H0P4 11.15,5.2 r270 top value=BLUE
LD8 "LED_yellow" LED_0603_OSRAM_LY-Q396-P1Q2-36_YELLOW_1A2K_H0P4 13.15,5.2 r270 top value=YELLOW
Mire1 "Comment" MIRE_PLACE_SMD_0P8MM 146.025,160.25 r0 top
Mire2 "Comment" MIRE_PLACE_SMD_0P8MM 1.825,153.975 r0 top
Mire3 "Comment" MIRE_PLACE_SMD_0P8MM 144.475,2.475 r0 top
Mire4 "Comment" MIRE_PLACE_SMD_0P8MM 2.325,154.125 r180 bottom
Mire5 "Comment" MIRE_PLACE_SMD_0P8MM 7.7,15.945 r180 bottom
Mire6 "Comment" MIRE_PLACE_SMD_0P8MM 142.375,3.25 r180 bottom
Q1 "" NPN_SOT23 53.7,160.2 r0 top value=9013-SOT23
Q2 "BSN20" MOS_SOT23 56.275,154 r90 top value=FDV303N
Q3 "STL9P3LLH6" MOS_POWERFLAT_3P3X3P3_P065 49.7,152.975 r90 top
Q4 "" MOS_POWERFLAT_3P3X3P3_P065 32.25,151.3 r180 top value=STL11N3LLH6
Q5 "STL9P3LLH6" MOS_POWERFLAT_3P3X3P3_P065 49.7,148.625 r90 top
Q6 "BSN20" MOS_SOT23 54.4,144.05 r90 top value=FDV303N
Q7 "BSN20" MOS_SOT23 123.15,91.25 r270 top value=FDV301N
Q8 "BSN20" MOS_SOT23 123.15,86.175 r270 top value=FDV301N
Q9 "" NPN_SOT23 111.8,37.2 r180 top value=9013-SOT23
Q10 "BSN20" MOS_SOT23 17.25,161.638 r90 bottom value=FDV303N
Q11 "BSN20" MOS_SOT23 17.25,157.613 r90 bottom value=FDV303N
Q12 "STL40DN3LLH5" PowerFLAT_5x6 23.85,152.175 r180 bottom
Q13 "STL40DN3LLH5" PowerFLAT_5x6 17.6,152.175 r180 bottom
Q14 "" NPN_SOT23 15.425,5.55 r0 bottom value=9013-SOT23
Q15 "" NPN_SOT23 11.175,5.55 r0 bottom value=9013-SOT23
Q16 "" NPN_SOT23 6.925,5.55 r0 bottom value=9013-SOT23
Q17 "" NPN_SOT23 2.675,5.55 r0 bottom value=9013-SOT23
R1 "" R0603 53.7,167.1 r90 top value=270R
R2 "" R0603 35.025,167.3 r180 top value=10K
R3 "Resistor" R0603 112.775,162.15 r90 top value=10K
R4 "" R0603 32.225,159.875 r0 top value=10K
R5 "" R0603 69.4,159.4 r270 top value=3K3
R6 "" R0603 100.05,159.4 r90 top value=3K3
R7 "" R0603 88.5,156.6 r90 top value=100K
R8 "" R0603 53.2,156.7 r0 top value=47K
R9 "" R0603 55.9,156.7 r0 top value=22K
R10 "" R0603 37.025,154.9 r0 top value=2K7
R11 "" R0603 39.4,154.2 r270 top value=330K
R12 "" R0603 40.9,154.2 r90 top value=49K9
R13 "" R0603 59.025,154 r270 top value=10K
R14 "Resistor" R0603 53.55,153.3 r270 top value=100R
R15 "" R0603 37.025,153.475 r0 top value=10K
R16 "" R0603 106.7,151.125 r90 top value=100K
R17 "" R0603 116.275,151.125 r90 top value=100K
R18 "" R0603 54.95,150.875 r270 top value=21K
R19 "" R0805 54.8,146.875 r0 top value=1K
R20 "" R0603 57.175,144.05 r270 top value=10K
R21 "" R0603 77.5,139.3 r90 top value=10K
R22 "" R0603 78.925,139.3 r90 top value=1K
R23 "" R0603 134.275,129.4 r90 top value=10K
R24 "" R0603 133.425,120.3 r0 top value=10K
R25 "" R0402 77.725,115.975 r270 top value=0R
R26 "" R0402 79.225,115.975 r270 top value=0R
R27 "" R0402 73,115.875 r270 top value=0R
R28 "" R0402 74.45,115.875 r270 top value=0R
R29 "" R0603 22.6,114.125 r180 top value=100K
R30 "" R0603 141.25,112.525 r180 top value=0R
R31 "" R0603 141.25,111.1 r180 top value=0R
R32 "" R0603 18.825,110.125 r0 top value=10K
R33 "" PHO_SENBAN_GL55XX 3.4,103.8 r270 top value=GL5528
R34 "" R0603 6.7,102.5 r270 top value=8K2
R35 "Resistor" R0603 129.1,97.925 r90 top value=120R
R36 "" R0603 74.15,97.225 r270 top value=10K
R37 "" R0603 75.85,97.225 r90 top value=10K
R38 "" R0603 82.85,97.225 r90 top value=220K
R39 "" R0603 13.5,97.5 r0 top value=1K
R40 "" R0603 142.65,96.875 r90 top value=22R
R41 "" R0603 144.1,96.875 r90 top value=1K
R42 "" R0603 129.1,95.575 r90 top value=150R
R43 "" R0603 8.7,95.3 r180 top value=1K
R44 "" R0603 8.7,93.8 r180 top value=1K
R45 "" R0603 38.6,91.3 r270 top value=10K
R46 "" R0603 142.65,91.125 r90 top value=22R
R47 "" R0603 144.125,91.125 r90 top value=1K
R48 "" R0402 120.475,91.225 r90 top value=4K7
R49 "Resistor" R0603 123.55,88.725 r0 top value=0R
R50 "" R0402 120.5,86.175 r90 top value=4K7
R51 "Resistor" R0603 123.55,83.625 r0 top value=0R
R52 "" R0603 120.825,81.725 r0 top value=10K
R53 "" R0603 135.05,81.25 r180 top value=22R
R54 "" R0603 135.05,79.825 r180 top value=22R
R55 "" R0603 135.05,78.375 r180 top value=1K
R56 "" R0603 19,77.8 r0 top value=20K
R57 "" R0603 16,77.8 r0 top value=10K2
R58 "" R0603 135.05,76.95 r180 top value=22R
R59 "" R0603 47.1,76.7 r0 top value=20K5
R60 "" R0603 44.6,76.7 r0 top value=11K8
R61 "" R0603 135.05,75.5 r0 top value=1K
R62 "" R0603 135.05,74.05 r180 top value=22R
R63 "" R0603 135.05,72.625 r180 top value=1K
R64 "" R0603 15.7,72.4 r0 top value=10K
R65 "" R0603 43.8,71.3 r0 top value=10K
R66 "" R0402 124.65,69.5 r180 top value=47R
R67 "Resistor" R0603 9.4,68.7 r0 top value=1K
R68 "" R0402 124.675,68.4 r0 top value=47R
R69 "" R0402 124.675,67.35 r180 top value=47R
R70 "" R0402 124.675,66.275 r180 top value=47R
R71 "" R0402 124.675,65.225 r180 top value=47R
R72 "" R0402 124.675,64.15 r180 top value=47R
R73 "" R0603 27.85,57.7 r270 top value=10K
R74 "" R0603 79.3,57 r90 top value=100K
R75 "" R0603 87,57 r270 top value=100K
R76 "" R0603 89.5,57 r90 top value=10K
R77 "" R0603 136.35,57.475 r0 top value=0R
R78 "" R0603 136.35,56.075 r0 top value=0R
R79 "" R0603 128.425,55.725 r180 top value=10K
R80 "" R0603 23,54.875 r90 top value=1K
R81 "" R0603 132.95,53.075 r90 top value=120R
R82 "" R0603 27.85,51.2 r270 top value=100K
R83 "" R0603 123.6,45.2 r270 top value=2K2
R84 "" R0603 126.4,45.2 r90 top value=100K
R85 "" R0603 116.5,42.6 r0 top value=10K
R86 "" R0603 77.6,41.5 r270 top value=100K
R87 "" R0603 79.1,41.5 r270 top value=100K
R88 "" R0603 83.4,41.5 r90 top value=100K
R89 "" R0603 88.1,41.5 r270 top value=10K
R90 "" R0603 89.6,41.5 r270 top value=10K
R91 "" R0603 111.8,41.9 r0 top value=1K
R92 "" R0603 24.7,40.25 r270 top value=10K
R93 "" R0603 111.8,40.4 r0 top value=22K
R94 "" R0603 75.5,39.1 r0 top value=10K
R95 "" R0603 78.1,39.1 r0 top value=10K
R96 "" R0603 23.275,37.95 r270 top value=10K
R97 "" R0402 27.4,37.625 r270 top value=100R
R98 "" R0603 128.9,37.3 r180 top value=49.9R
R99 "" R0603 128.9,35.9 r180 top value=49.9R
R100 "" R0402 20.225,35.8 r180 top value=4K7
R101 "" R0402 20.225,34.75 r180 top value=4K7
R102 "" R0603 120.8,34 r270 top value=10K
R103 "" R0402 37.375,34.4 r180 top value=0R
R104 "" R0603 111.1,34.1 r180 top value=47K
R105 "" R0603 136.5,33.3 r270 top value=1K
R106 "" R0402 16.875,33.05 r90 top value=2K7
R107 "" R0402 17.925,33.05 r90 top value=4K7
R108 "" R0603 144.9,32.6 r90 top value=3K3
R109 "PT100" R0603_H0P45 146.9,31.875 r90 top value="PTS 100R @ 0°C"
R110 "" R0603 37.05,32 r180 top value=100K
R111 "" R0603 136.6,30.3 r90 top value=1K
R112 "" R0603 144.9,30.2 r90 top value=100R
R113 "" R0402 37.375,30.075 r180 top value=0R
R114 "" R0402 37.375,26.9 r180 top value=100R
R115 "" R0402 26.8,24.6 r90 top value=3K
R116 "" R0402 30.35,24.6 r270 top value=100R
R117 "" R0402 24.35,24.6 r90 top value=100R
R118 "" R0603 128.2,18.975 r180 top value=100K
R119 "" R0603 111.225,16.625 r270 top value=10K
R120 "" R0603 112.65,16.625 r90 top value=0R
R121 "" R0603 114.1,16.625 r90 top value=0R
R122 "" R0603 128.2,13.8 r180 top value=100K
R123 "" R0603 56.7,12.2 r270 top value=200R
R124 "" R0603 58.5,12.2 r270 top value=100K
R125 "" R0603 70.2,11.4 r270 top value=200R
R126 "" R0603 72.1,11.4 r270 top value=20K
R127 "Resistor" R0603 139.125,11.725 r0 top value=10K
R128 "" R0402 3.15,10.25 r90 top value=330R
R129 "" R0402 4.65,10.25 r90 top value=330R
R130 "" R0603 7.25,8.4 r90 top value=270R
R131 "" R0603 9.15,8.4 r90 top value=360R
R132 "" R0603 11.15,8.4 r90 top value=360R
R133 "Resistor" R0603 13.15,8.4 r90 top value=470R
R134 "" R0603 132.7,163.5 r90 bottom value=0R
R135 "" R0603 130.1,163.5 r90 bottom value=0R
R136 "" R0603 14.375,161.638 r270 bottom value=10K
R137 "" R0603 14.375,157.613 r90 bottom value=10K
R138 "Resistor" R0805_H0P5 37.925,154.375 r0 bottom value=0R047
R139 "Resistor" R0402 43.325,153.7 r180 bottom value=0R
R140 "Resistor" R0402 43.325,152.625 r180 bottom value=0R
R141 "Resistor" R0603 38.4,151.975 r180 bottom value=2K4
R142 "" R0603 38.4,150.55 r0 bottom value=10K
R143 "" R0603 98.975,143.6 r90 bottom value=0R
R144 "" R0603 96.1,143.6 r90 bottom value=0R
R145 "Resistor" R0402 114.6,137.375 r180 bottom value=0R
R146 "" R0603 149.1,133.2 r270 bottom value=0R
R147 "Resistor" R0603 38.325,132.3 r180 bottom value=2K7
R148 "" R0402 117.925,131.05 r0 bottom value=0R
R149 "Resistor" R0603 38.308,130.85 r180 bottom value=2K7
R150 "" R0402 109.45,129.9 r0 bottom value=0R
R151 "" R0402 114.3,129.75 r0 bottom value=0R
R152 "" R0402 117.925,128.5 r0 bottom value=0R
R153 "" R0603 35.75,127.5 r180 bottom value=0R
R154 "" R0603 35.75,126.05 r180 bottom value=0R
R155 "" R0402 114.6,125.95 r0 bottom value=0R
R156 "" R0603 110.4,125.3 r270 bottom value=820R
R157 "" R0603 35.75,124.625 r180 bottom value=0R
R158 "" R0402 118.175,124.425 r0 bottom value=0R
R159 "" R0402 114.4,122.625 r0 bottom value=0R
R160 "" R0402 109.25,122.15 r0 bottom value=0R
R161 "" R0603 17.55,121.475 r0 bottom value=0R
R162 "" R0402 109.25,120.875 r0 bottom value=0R
R163 "" R0402 118.175,120.475 r0 bottom value=0R
R164 "" R0402 114.367,119.716 r0 bottom value=0R
R165 "" R0603 130.125,119.5 r180 bottom value=47K
R166 "" R0603 130.125,118.05 r180 bottom value=47K
R167 "" R0603 20.75,117.975 r0 bottom value=100K
R168 "" R0603 114.725,117.075 r0 bottom value=0R
R169 "" R0603 130.125,116.625 r180 bottom value=47K
R170 "" R0603 20.75,116.475 r0 bottom value=100K
R171 "" R0603 118,115.4 r180 bottom value=0R
R172 "" R0603 130.125,115.175 r180 bottom value=47K
R173 "" R0603 130.125,113.75 r180 bottom value=47K
R174 "" R0603 145.025,110.85 r180 bottom value=10K
R175 "Resistor" R0402 101.575,105.3 r0 bottom value=0R
R176 "" R0603 60.25,104.8 r180 bottom value=0R
R177 "Resistor" R0402 129.875,104.6 r90 bottom value=0R
R178 "Resistor" R0402 120.2,104.6 r90 bottom value=0R
R179 "Resistor" R0402 119.125,104.6 r90 bottom value=0R
R180 "Resistor" R0402 96.075,104.5 r0 bottom value=0R
R181 "" R0603 60.25,103.375 r180 bottom value=0R
R182 "Resistor" R0402 96.075,103.175 r0 bottom value=0R
R183 "Resistor" R0402 101.575,102.425 r0 bottom value=0R
R184 "" R0603 60.25,101.925 r180 bottom value=0R
R185 "Resistor" R0402 96.075,101.95 r0 bottom value=0R
R186 "Resistor" R0402 101.575,101.35 r0 bottom value=0R
R187 "" R0603 54.125,100.675 r0 bottom value=0R
R188 "Resistor" R0402 96.075,100.675 r0 bottom value=0R
R189 "Resistor" R0402 59.925,100.675 r180 bottom value=0R
R190 "Resistor" R0402 101.575,100.275 r0 bottom value=0R
R191 "Resistor" R0402 59.925,98.15 r0 bottom value=0R
R192 "Resistor" R0402 101.575,98.125 r0 bottom value=0R
R193 "Resistor" R0402 96.075,98.125 r0 bottom value=0R
R194 "" R0603 60.25,96.9 r180 bottom value=0R
R195 "" R0603 122.034,96.771 r180 bottom value=10K
R196 "Resistor" R0402 101.575,96.875 r0 bottom value=0R
R197 "Resistor" R0402 96.075,96.875 r0 bottom value=0R
R198 "Resistor" R0402 59.925,95.65 r180 bottom value=0R
R199 "Resistor" R0402 101.575,95.6 r0 bottom value=0R
R200 "Resistor" R0402 96.075,95.6 r0 bottom value=0R
R201 "" R0603 131.634,95.371 r180 bottom value=10K
R202 "" R0603 50.709,95.346 r180 bottom value=0R
R203 "Resistor" R0402 96.075,94.35 r180 bottom value=0R
R204 "Resistor" R0402 101.575,94.325 r0 bottom value=0R
R205 "Resistor" R0402 59.925,94.325 r0 bottom value=0R
R206 "" R0603 50.709,93.921 r180 bottom value=0R
R207 "Resistor" R0402 101.575,93.075 r0 bottom value=0R
R208 "Resistor" R0402 59.925,93.075 r0 bottom value=0R
R209 "Resistor" R0402 96.075,93.05 r180 bottom value=0R
R210 "" R0603 50.709,92.471 r180 bottom value=0R
R211 "" R0603 128.209,91.571 r90 bottom value=0R
R212 "" R0603 126.734,91.571 r270 bottom value=0R
R213 "Resistor" R0402 101.575,91.8 r0 bottom value=0R
R214 "Resistor" R0402 59.925,91.8 r0 bottom value=0R
R215 "Resistor" R0402 96.075,91.775 r180 bottom value=0R
R216 "" R0603 50.709,91.071 r180 bottom value=0R
R217 "Resistor" R0402 101.575,90.525 r180 bottom value=0R
R218 "Resistor" R0402 59.925,90.525 r0 bottom value=0R
R219 "Resistor" R0402 96.075,90.525 r180 bottom value=0R
R220 "" R0603 50.709,89.646 r180 bottom value=0R
R221 "Resistor" R0402 96.075,89.275 r180 bottom value=0R
R222 "Resistor" R0402 101.575,89.25 r180 bottom value=0R
R223 "Resistor" R0402 59.925,89.25 r0 bottom value=0R
R224 "Resistor" R0402 50.384,88.396 r180 bottom value=0R
R225 "Resistor" R0402 96.075,88 r180 bottom value=0R
R226 "Resistor" R0402 101.575,87.975 r180 bottom value=0R
R227 "Resistor" R0402 59.925,87.975 r0 bottom value=0R
R228 "Resistor" R0402 50.384,87.296 r180 bottom value=0R
R229 "Resistor" R0402 101.575,86.7 r180 bottom value=0R
R230 "" R0603 145.8,86.2 r0 bottom value=10K
R231 "" R0603 43.5,85 r180 bottom value=10K
R232 "" R0603 145.8,84.8 r180 bottom value=10K
R233 "" R0603 43.5,83.575 r180 bottom value=10K
R234 "" R0603 43.5,82.125 r180 bottom value=510R
R235 "" R0603 146,77.5 r0 bottom value=10K
R236 "" R0603 146,75 r0 bottom value=10K
R237 "" R0603 15.425,9.775 r180 bottom value=47K
R238 "" R0603 11.175,9.775 r180 bottom value=47K
R239 "" R0603 6.925,9.775 r180 bottom value=47K
R240 "" R0603 2.7,9.775 r180 bottom value=47K
R241 "" R0603 15.425,8.275 r180 bottom value=100K
R242 "" R0603 11.175,8.275 r180 bottom value=100K
R243 "" R0603 6.925,8.275 r180 bottom value=100K
R244 "" R0603 2.7,8.275 r180 bottom value=100K
R245 "Resistor" R0603 28.295,145.733 r270 bottom value=4K7
R246 "Resistor" R0603 14.756,146.528 r90 bottom value=4K7
R247 "Resistor" R0805 6.309,42.562 r180 top value=0R
R248 "" R0603 11.258,47.709 r0 top value=10K
R249 "Resistor" R0402 3.273,47.831 r180 top value=1M
R250 "Resistor" R0402 3.273,48.862 r0 top value=0R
